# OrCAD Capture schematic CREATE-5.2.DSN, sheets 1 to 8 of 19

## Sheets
1 P02: ASPEN-MEM/USB/LCD: size Custom; title: ASPEN-MEM/LCD; rev: 3.0; note: Kinoma Create
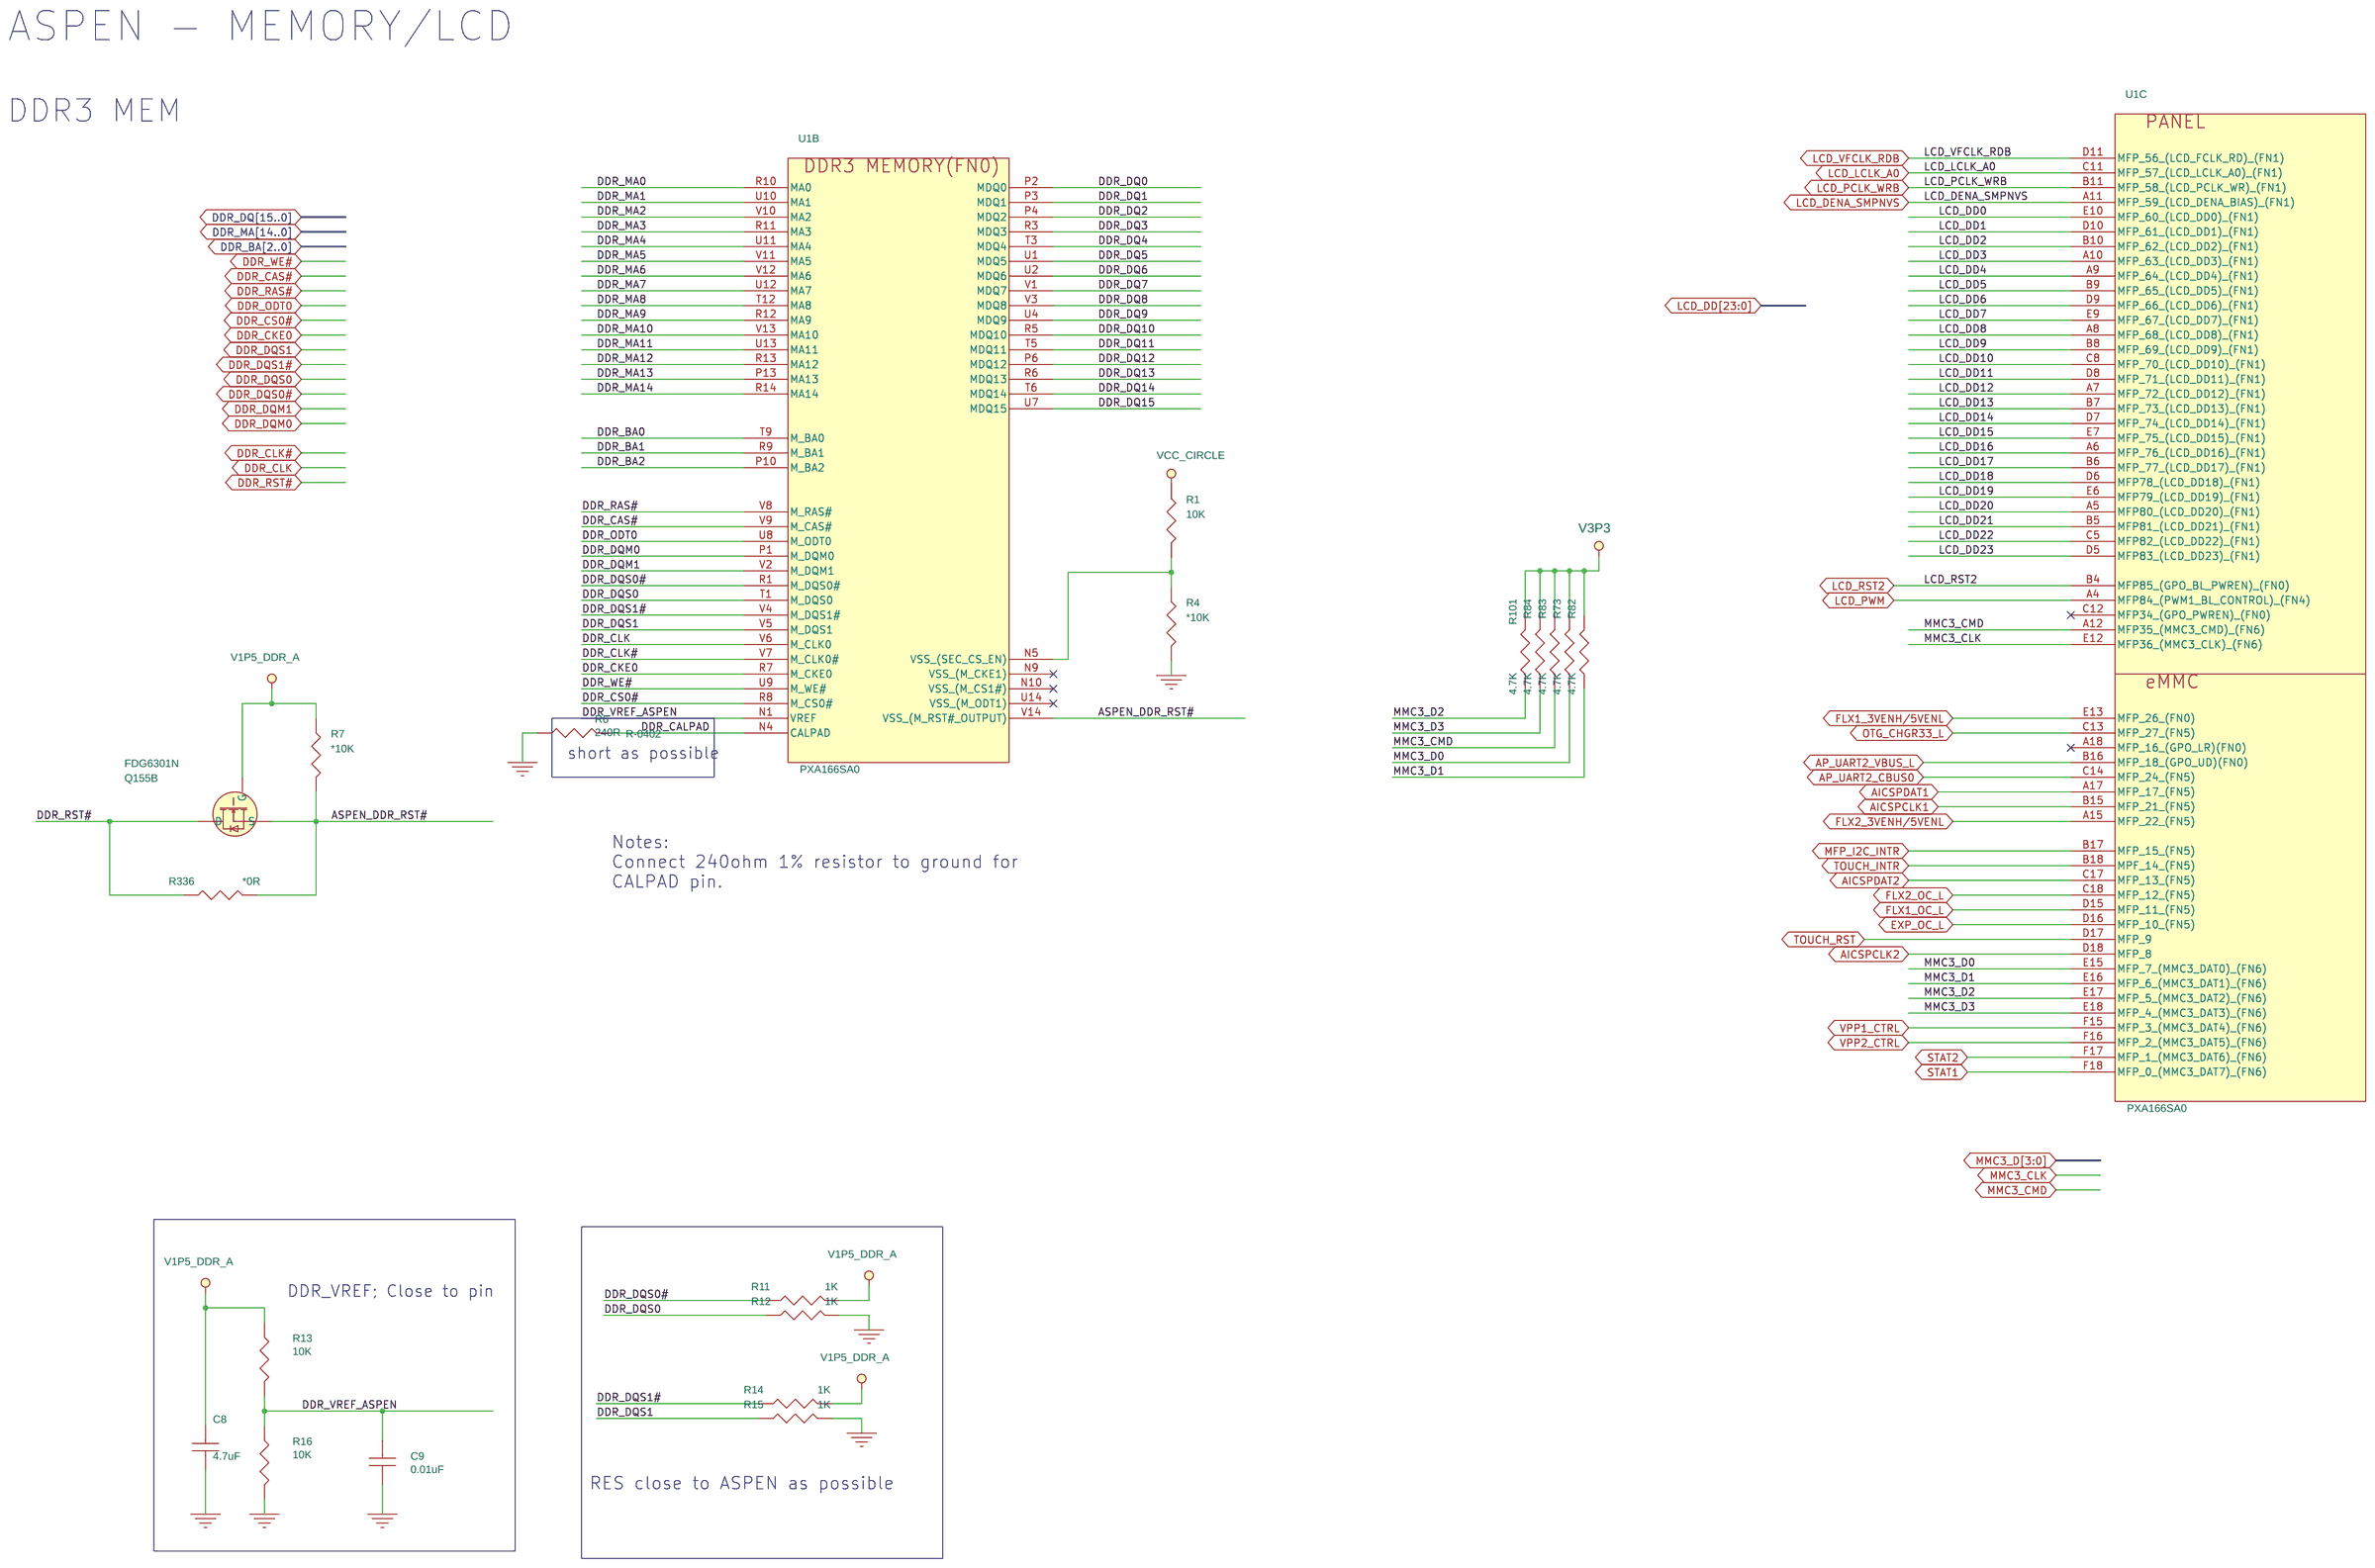
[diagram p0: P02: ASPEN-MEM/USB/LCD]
2 P04: ASPEN - Power: size Custom; title: ASPEN-Power
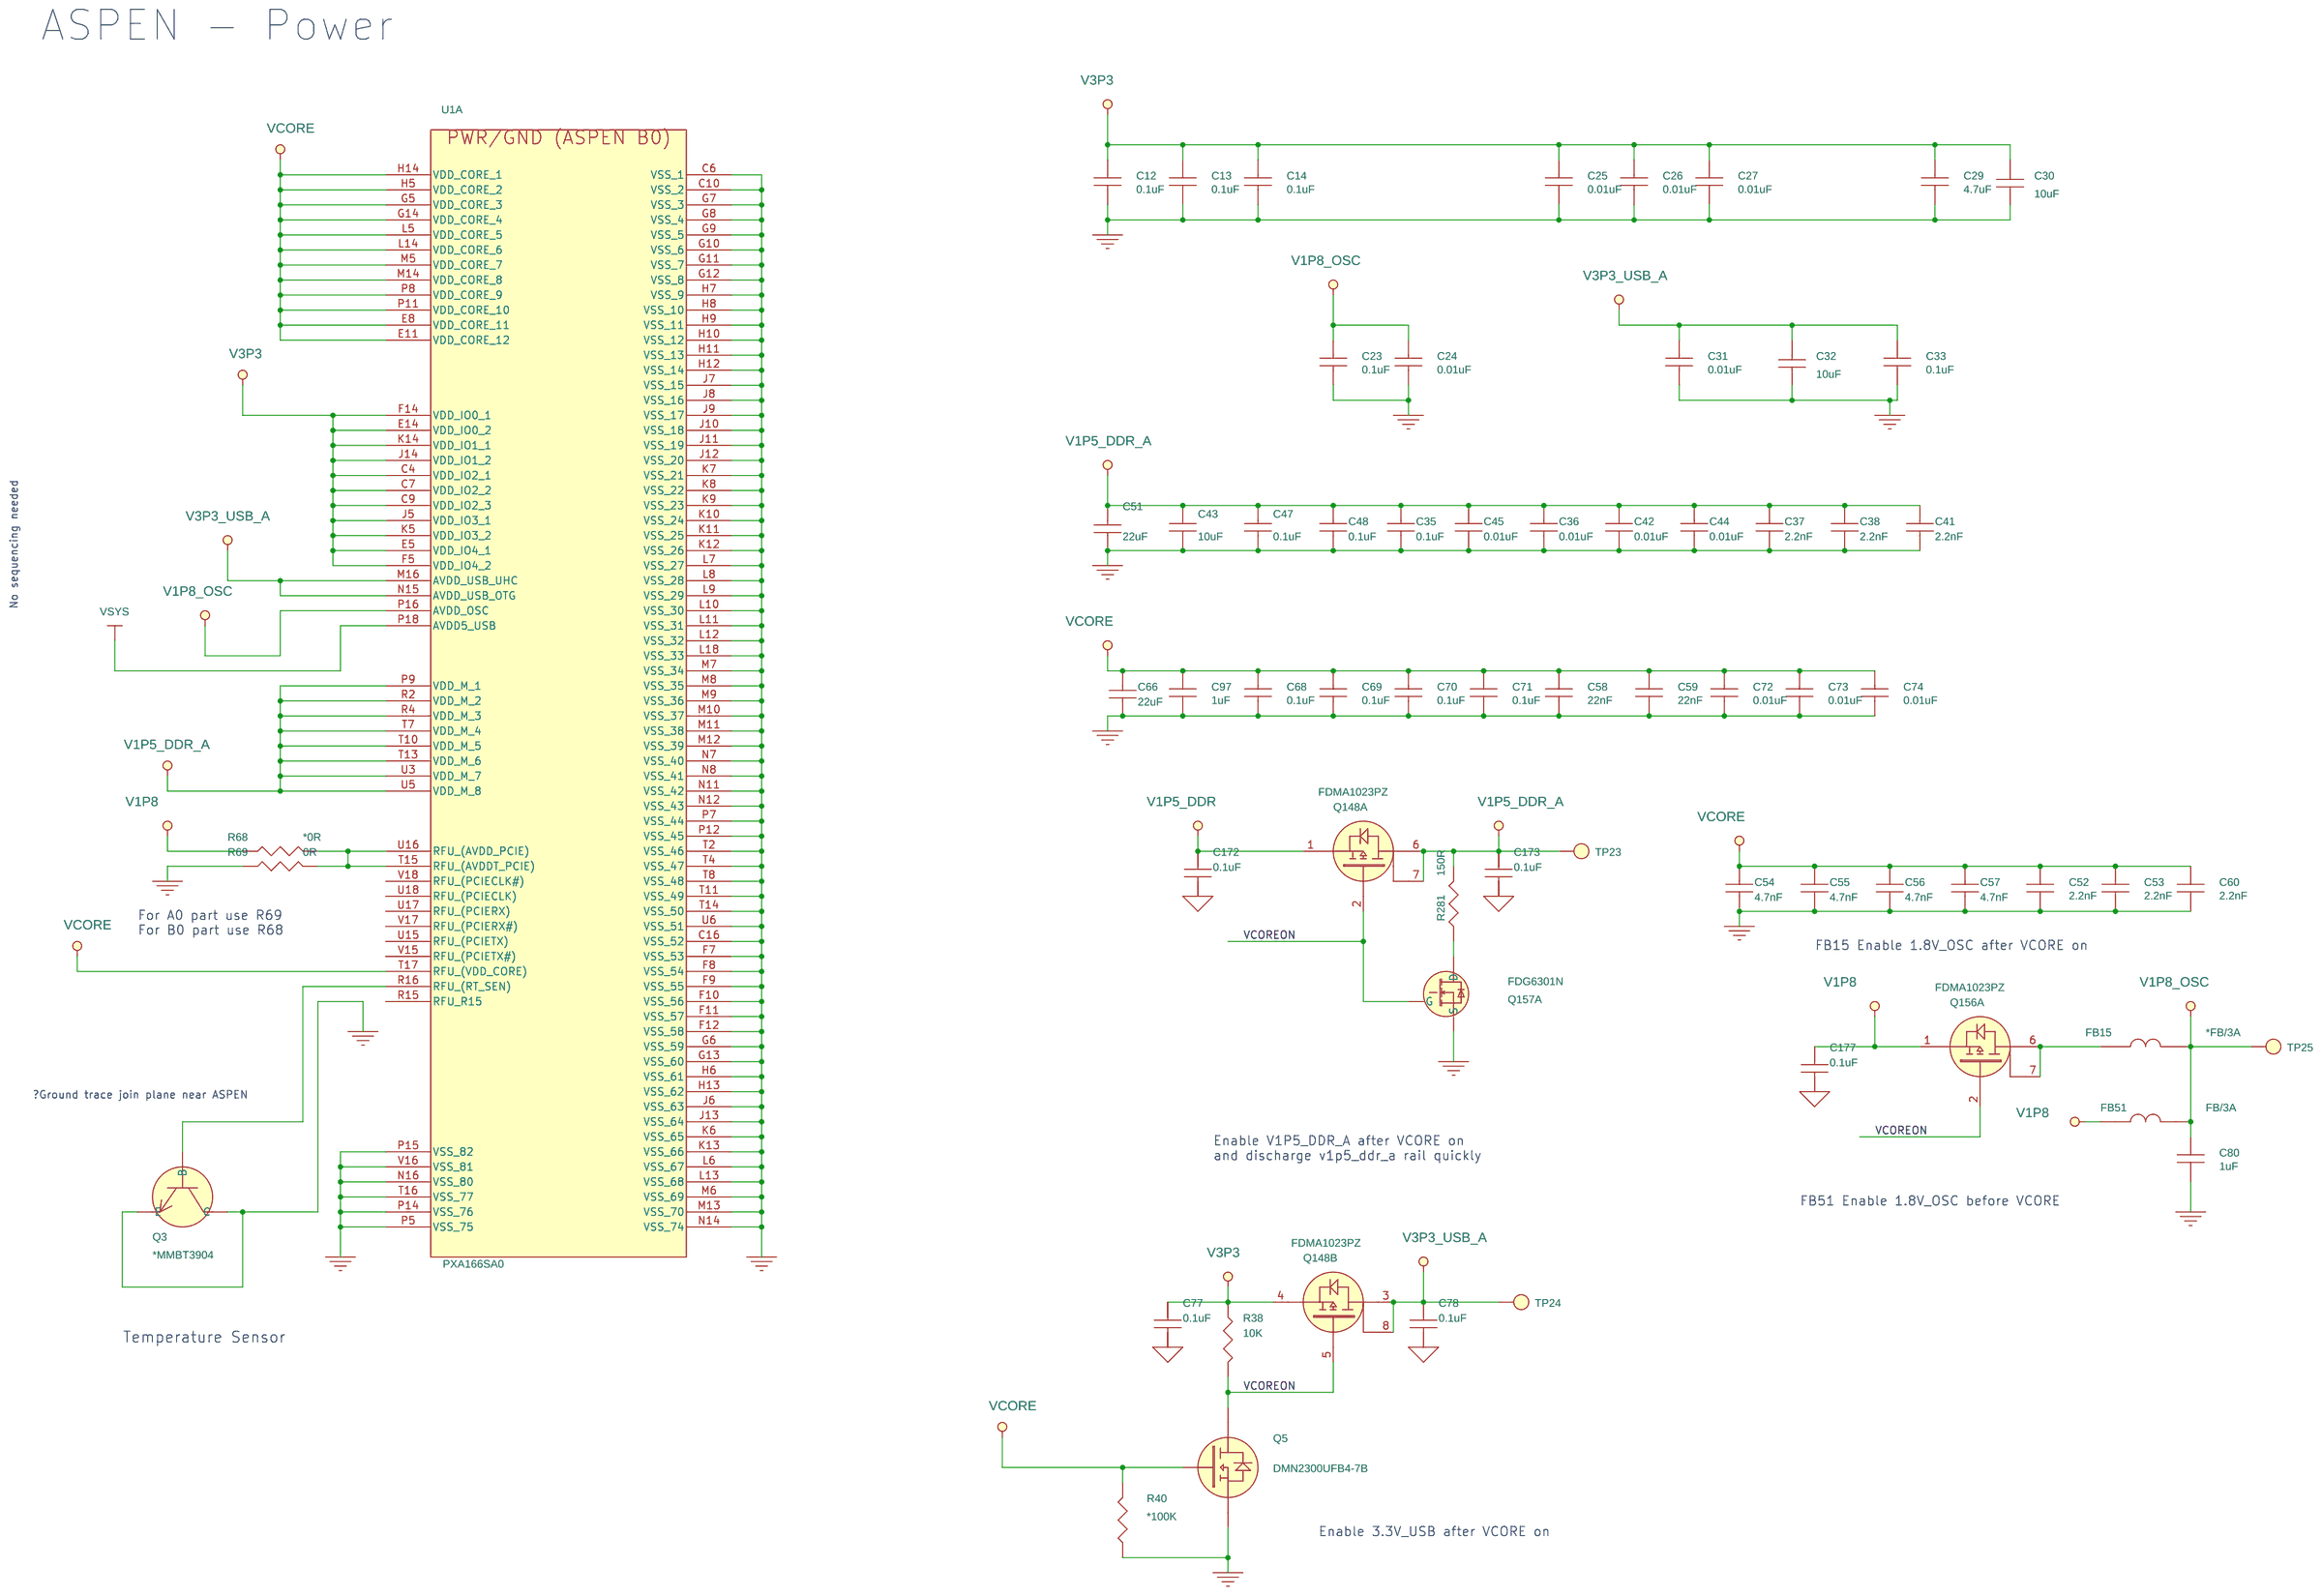
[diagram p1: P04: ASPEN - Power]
3 P06: Wifi 8887: size Custom; title: Wifi
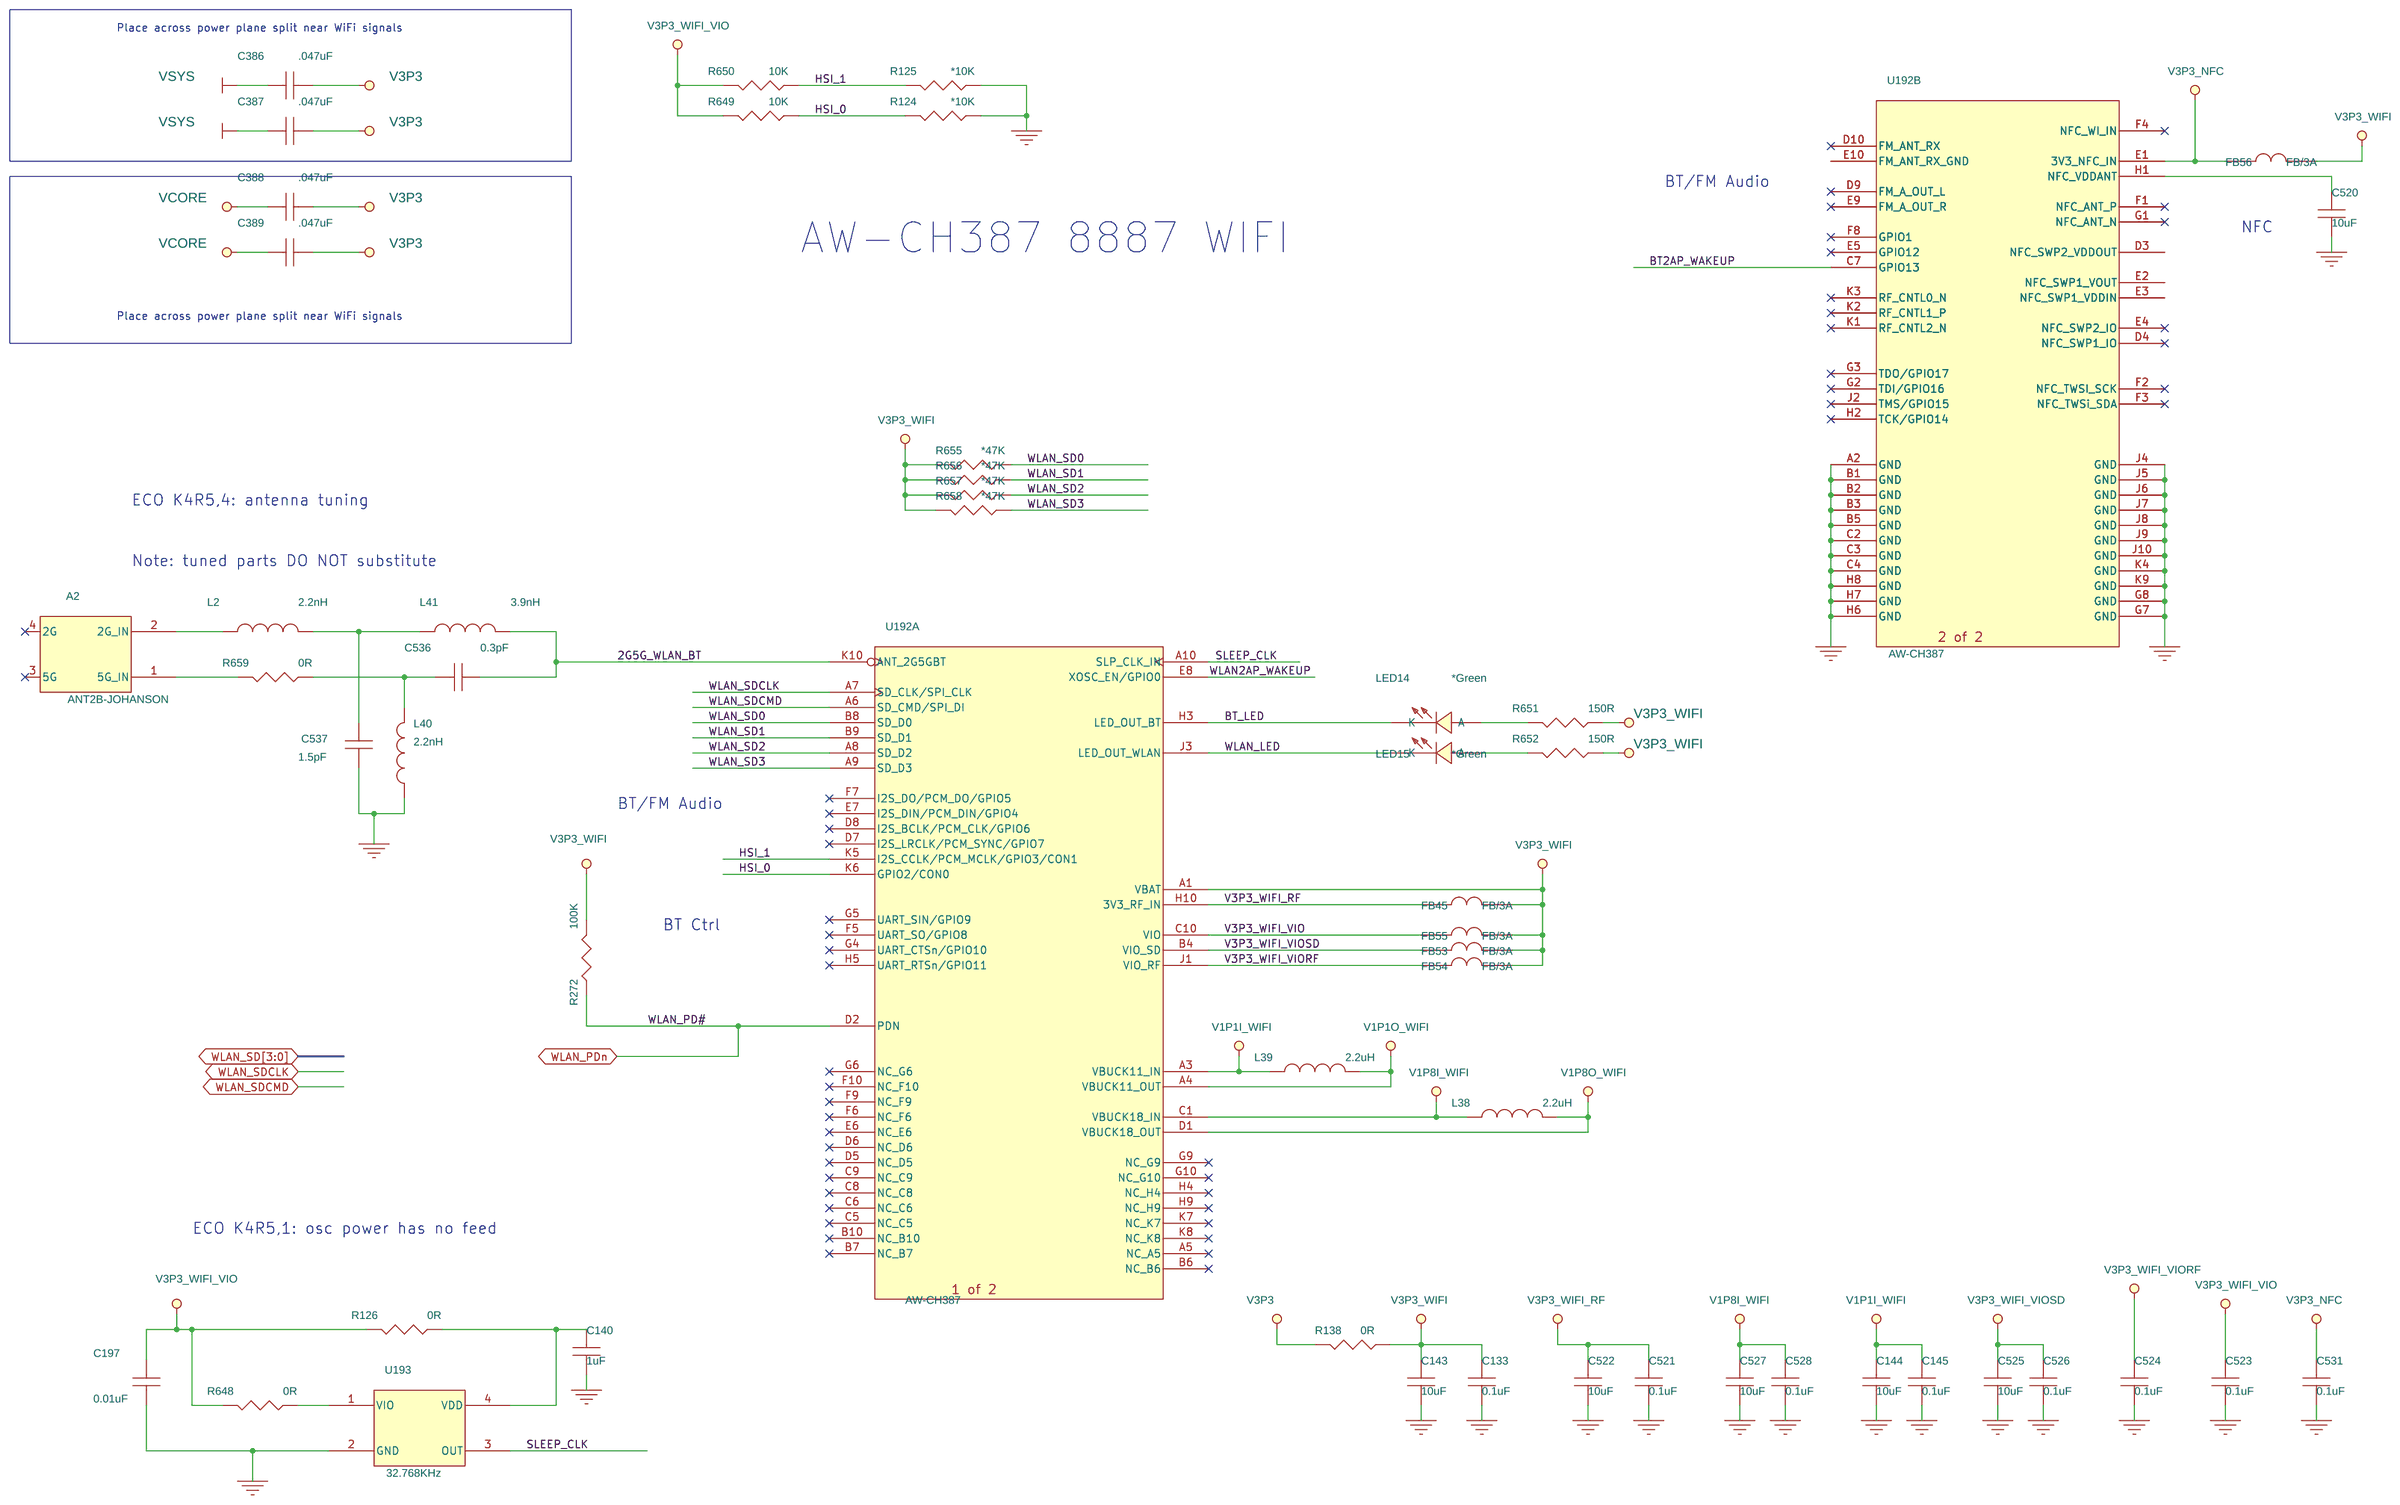
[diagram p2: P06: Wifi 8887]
4 P07: Audio: size Custom; title: Audio
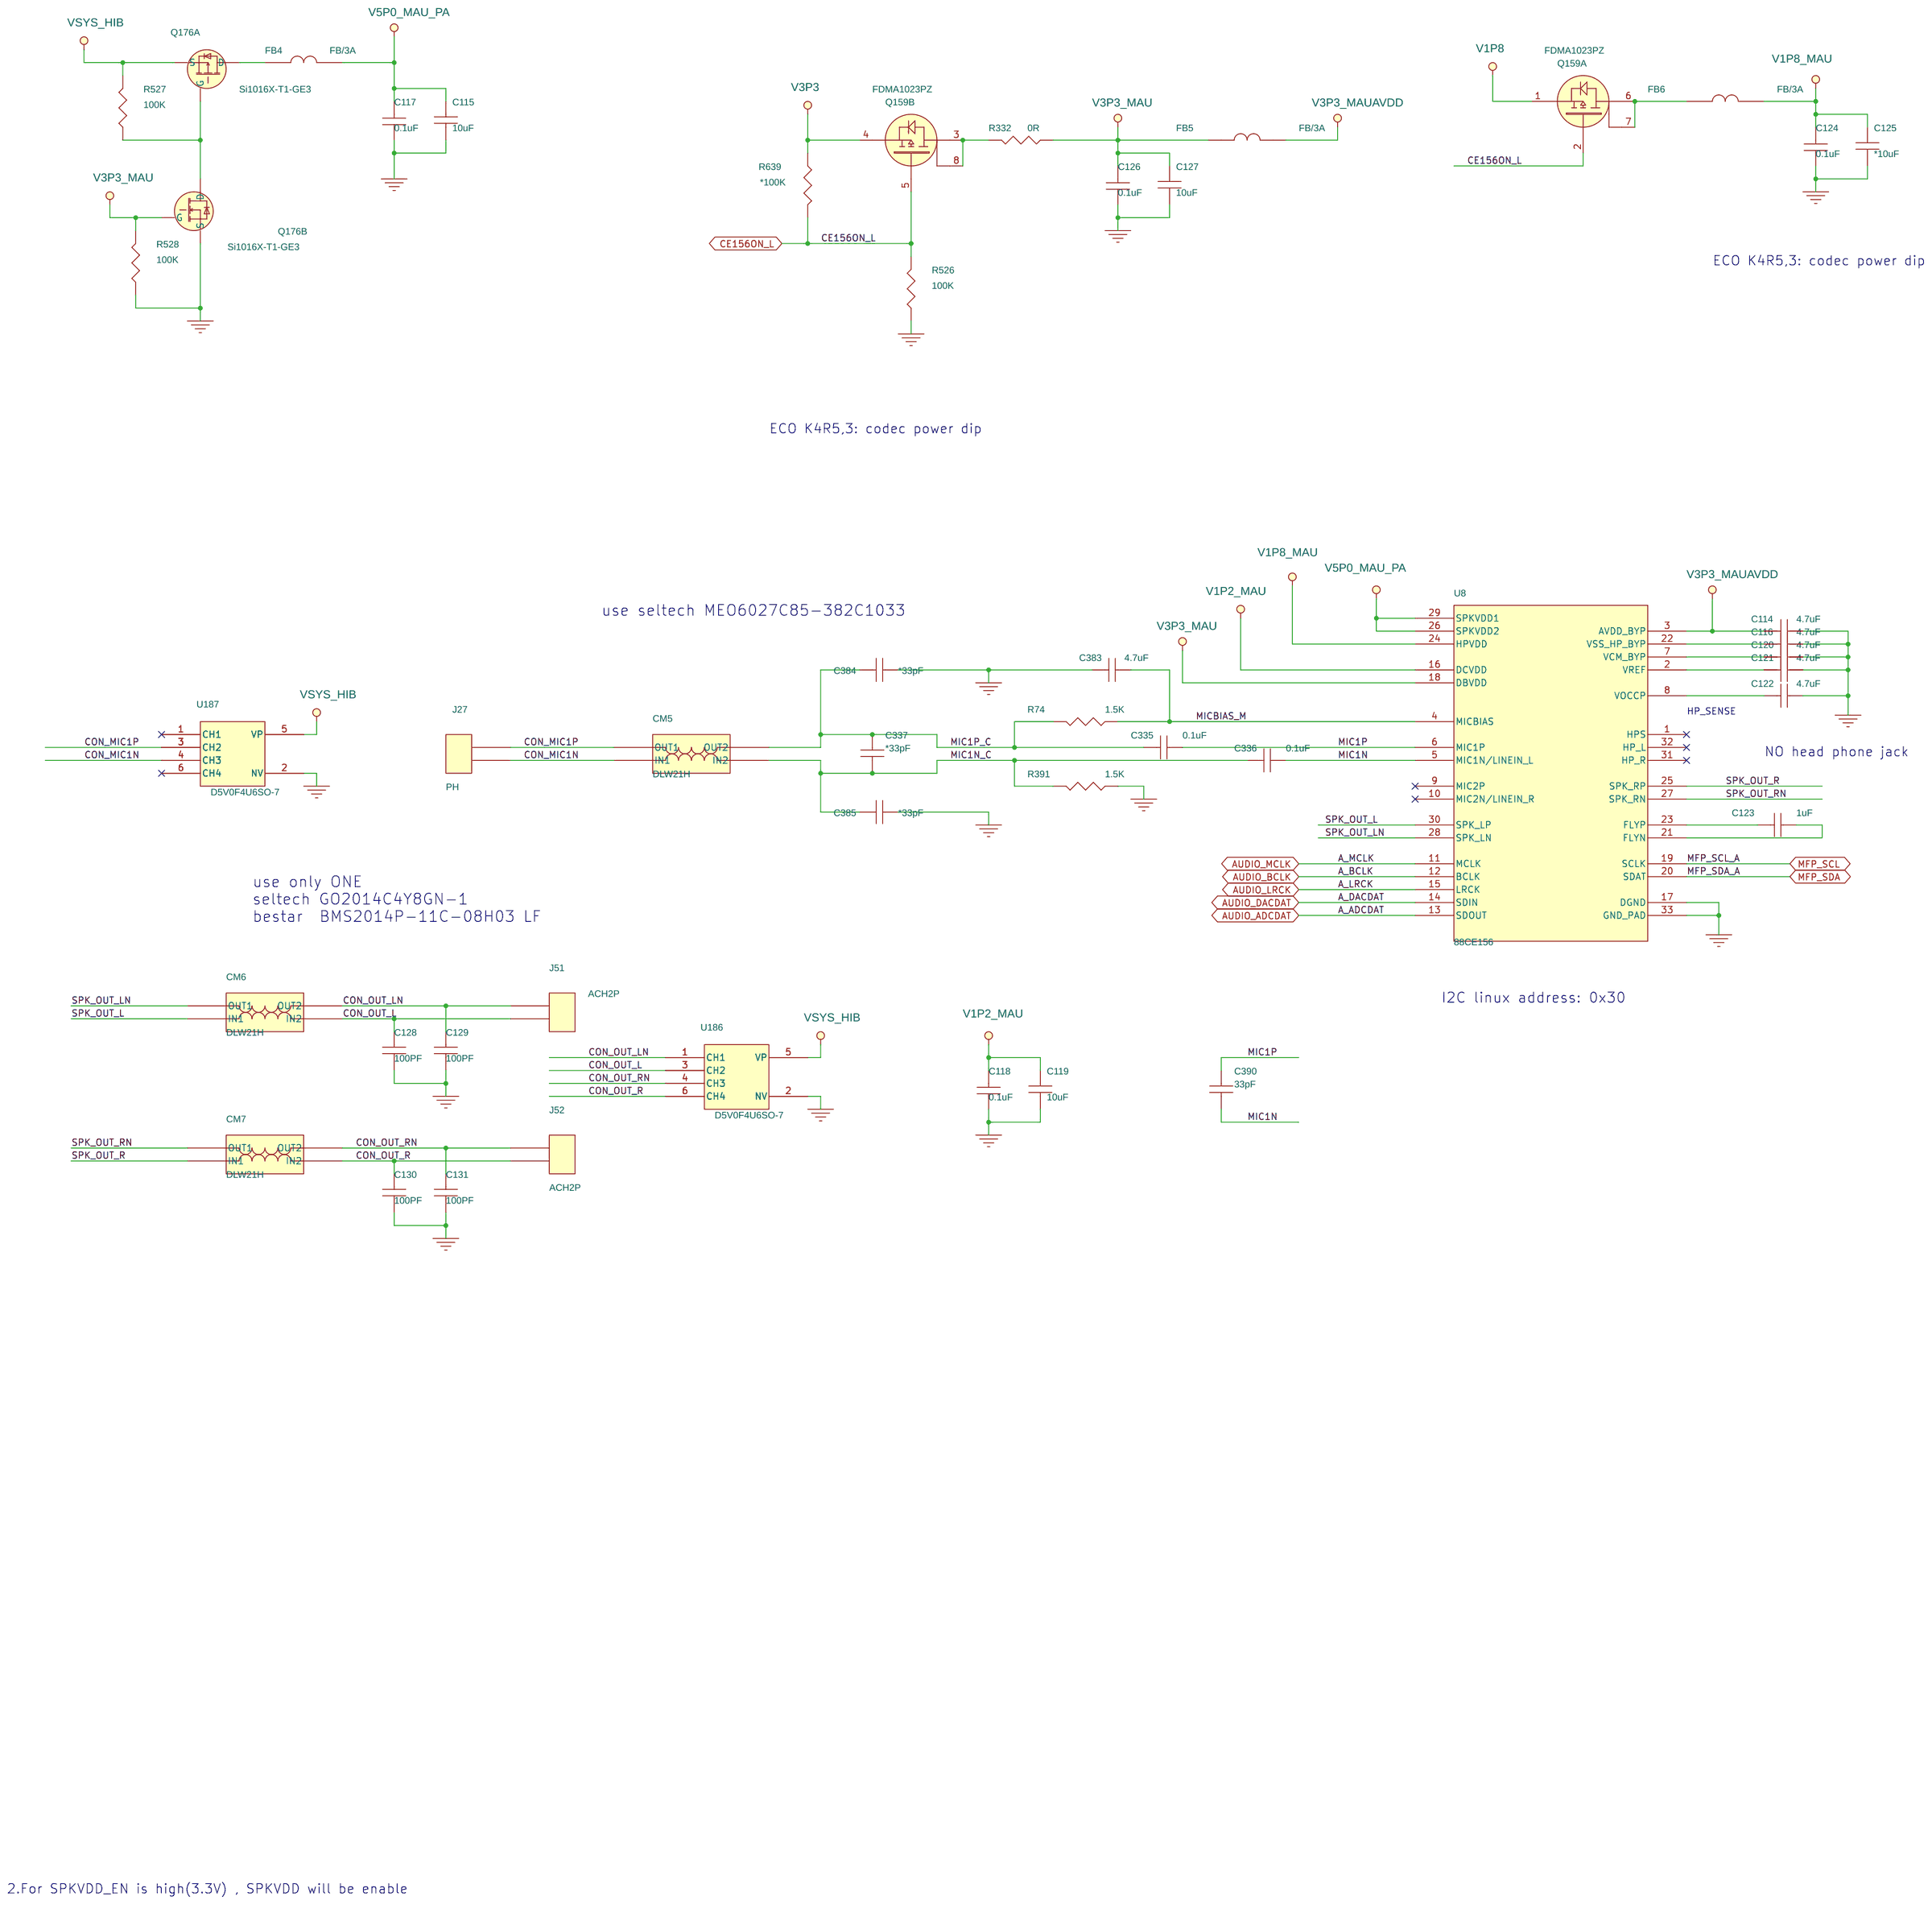
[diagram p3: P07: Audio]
5 P05: DDR3 SPI SD: size Custom; title: DDR3 SDRAM
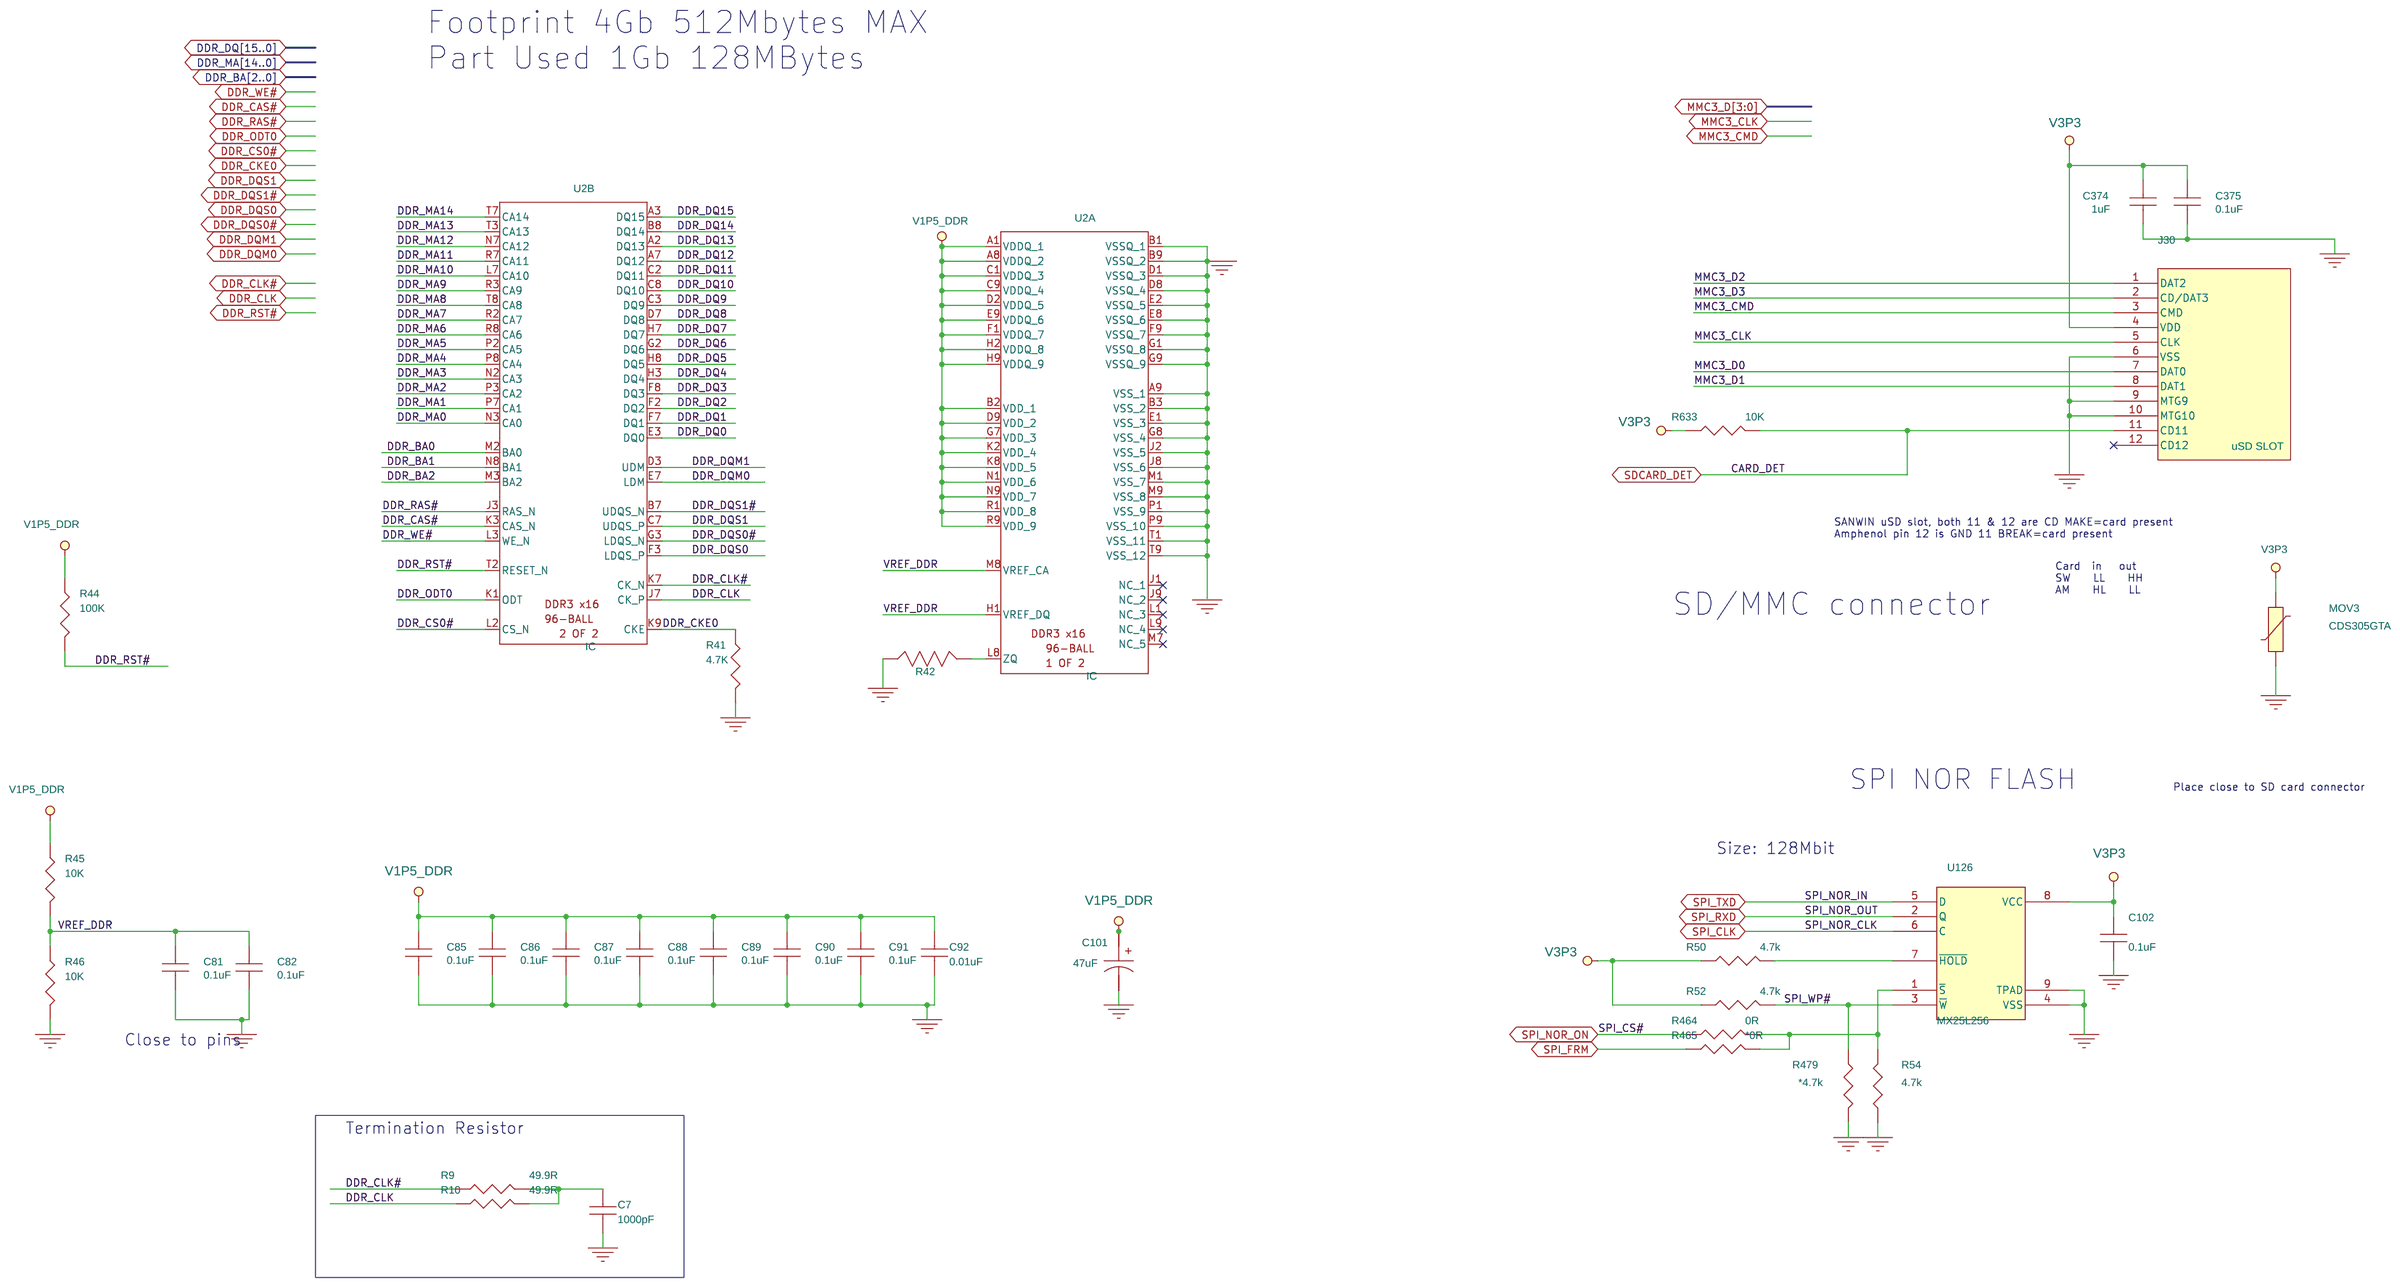
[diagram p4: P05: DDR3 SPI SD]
6 P08: LCD connections: size Custom; title: LCD & Touch
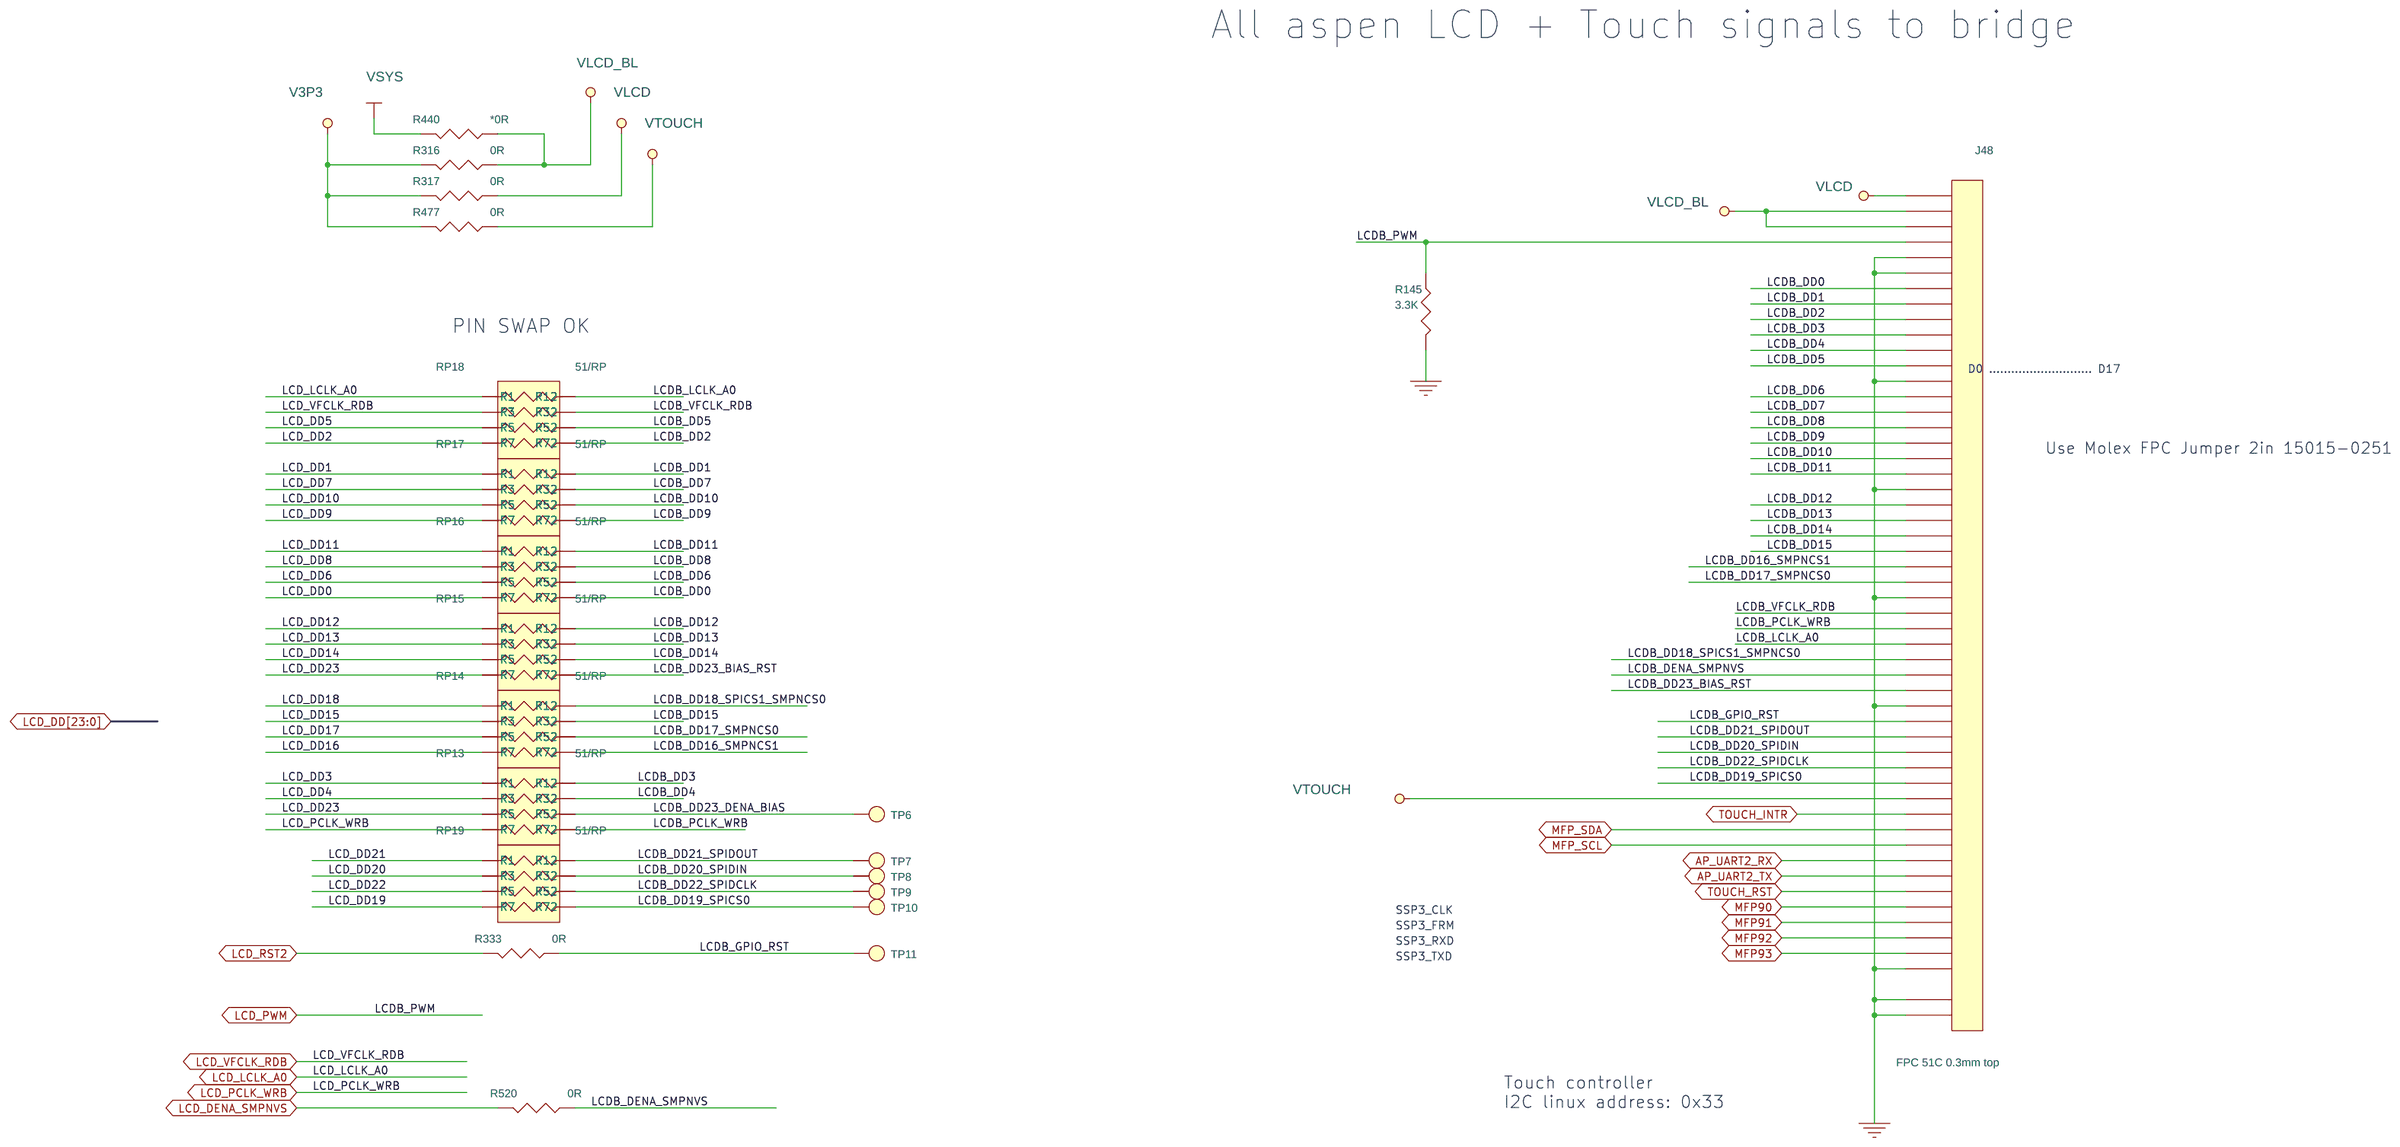
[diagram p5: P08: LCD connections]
7 P17: PIC Programmer: size B; title: PIC Programmer
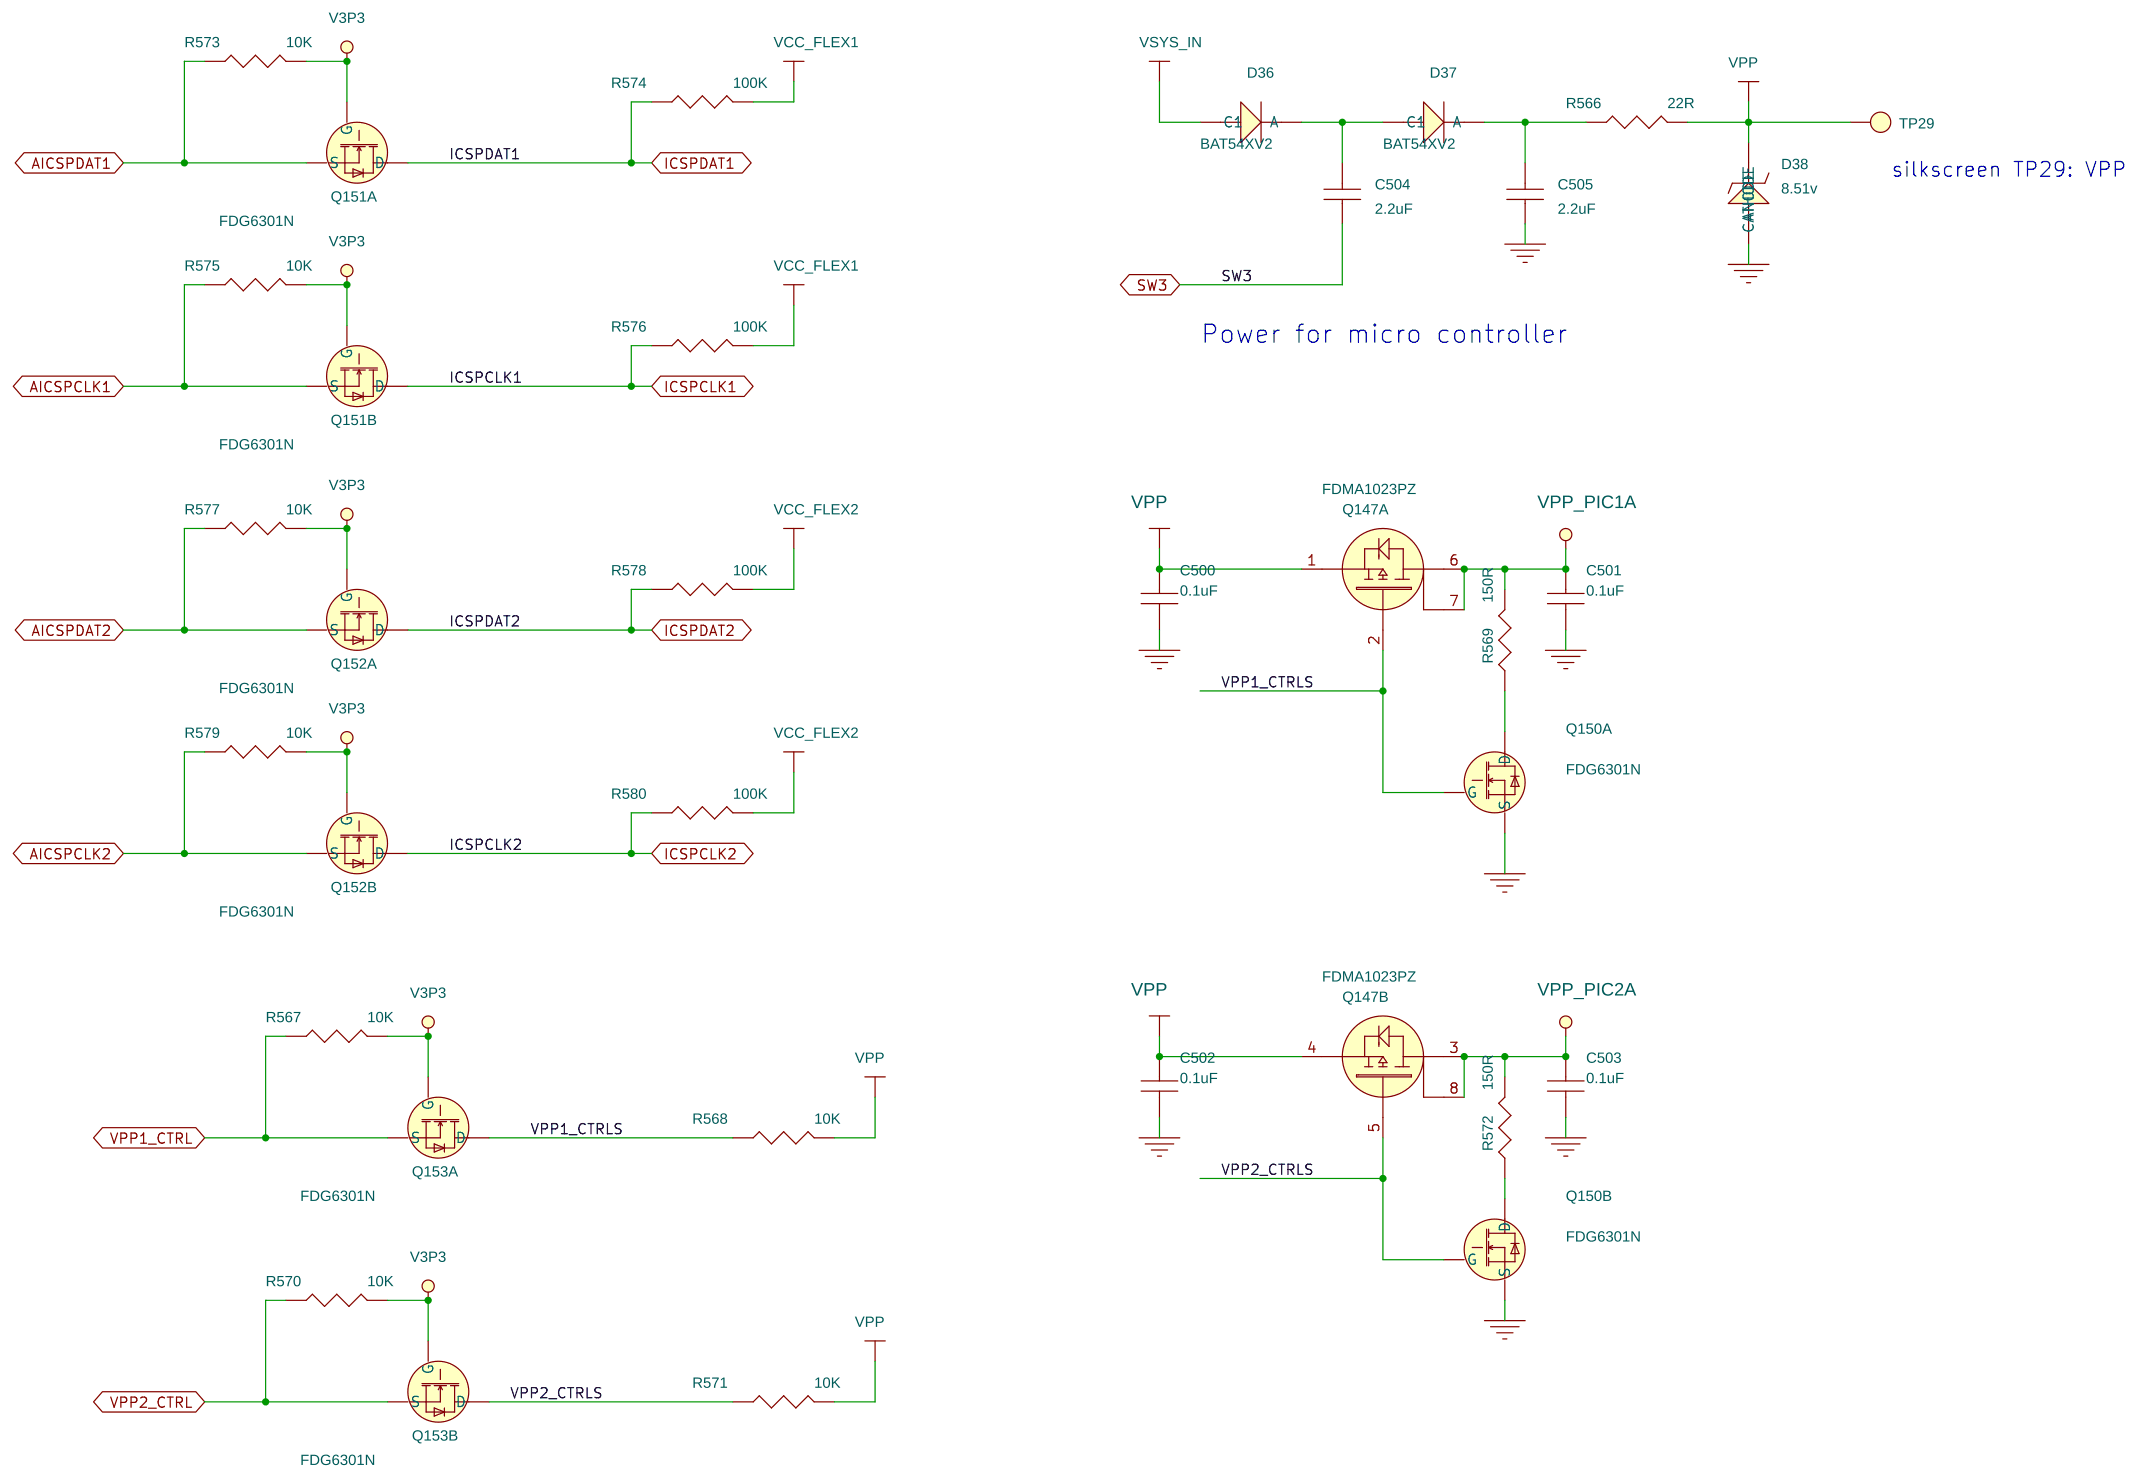
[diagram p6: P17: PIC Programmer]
8 P13: Debug + console: size Custom; title: Debug/Console
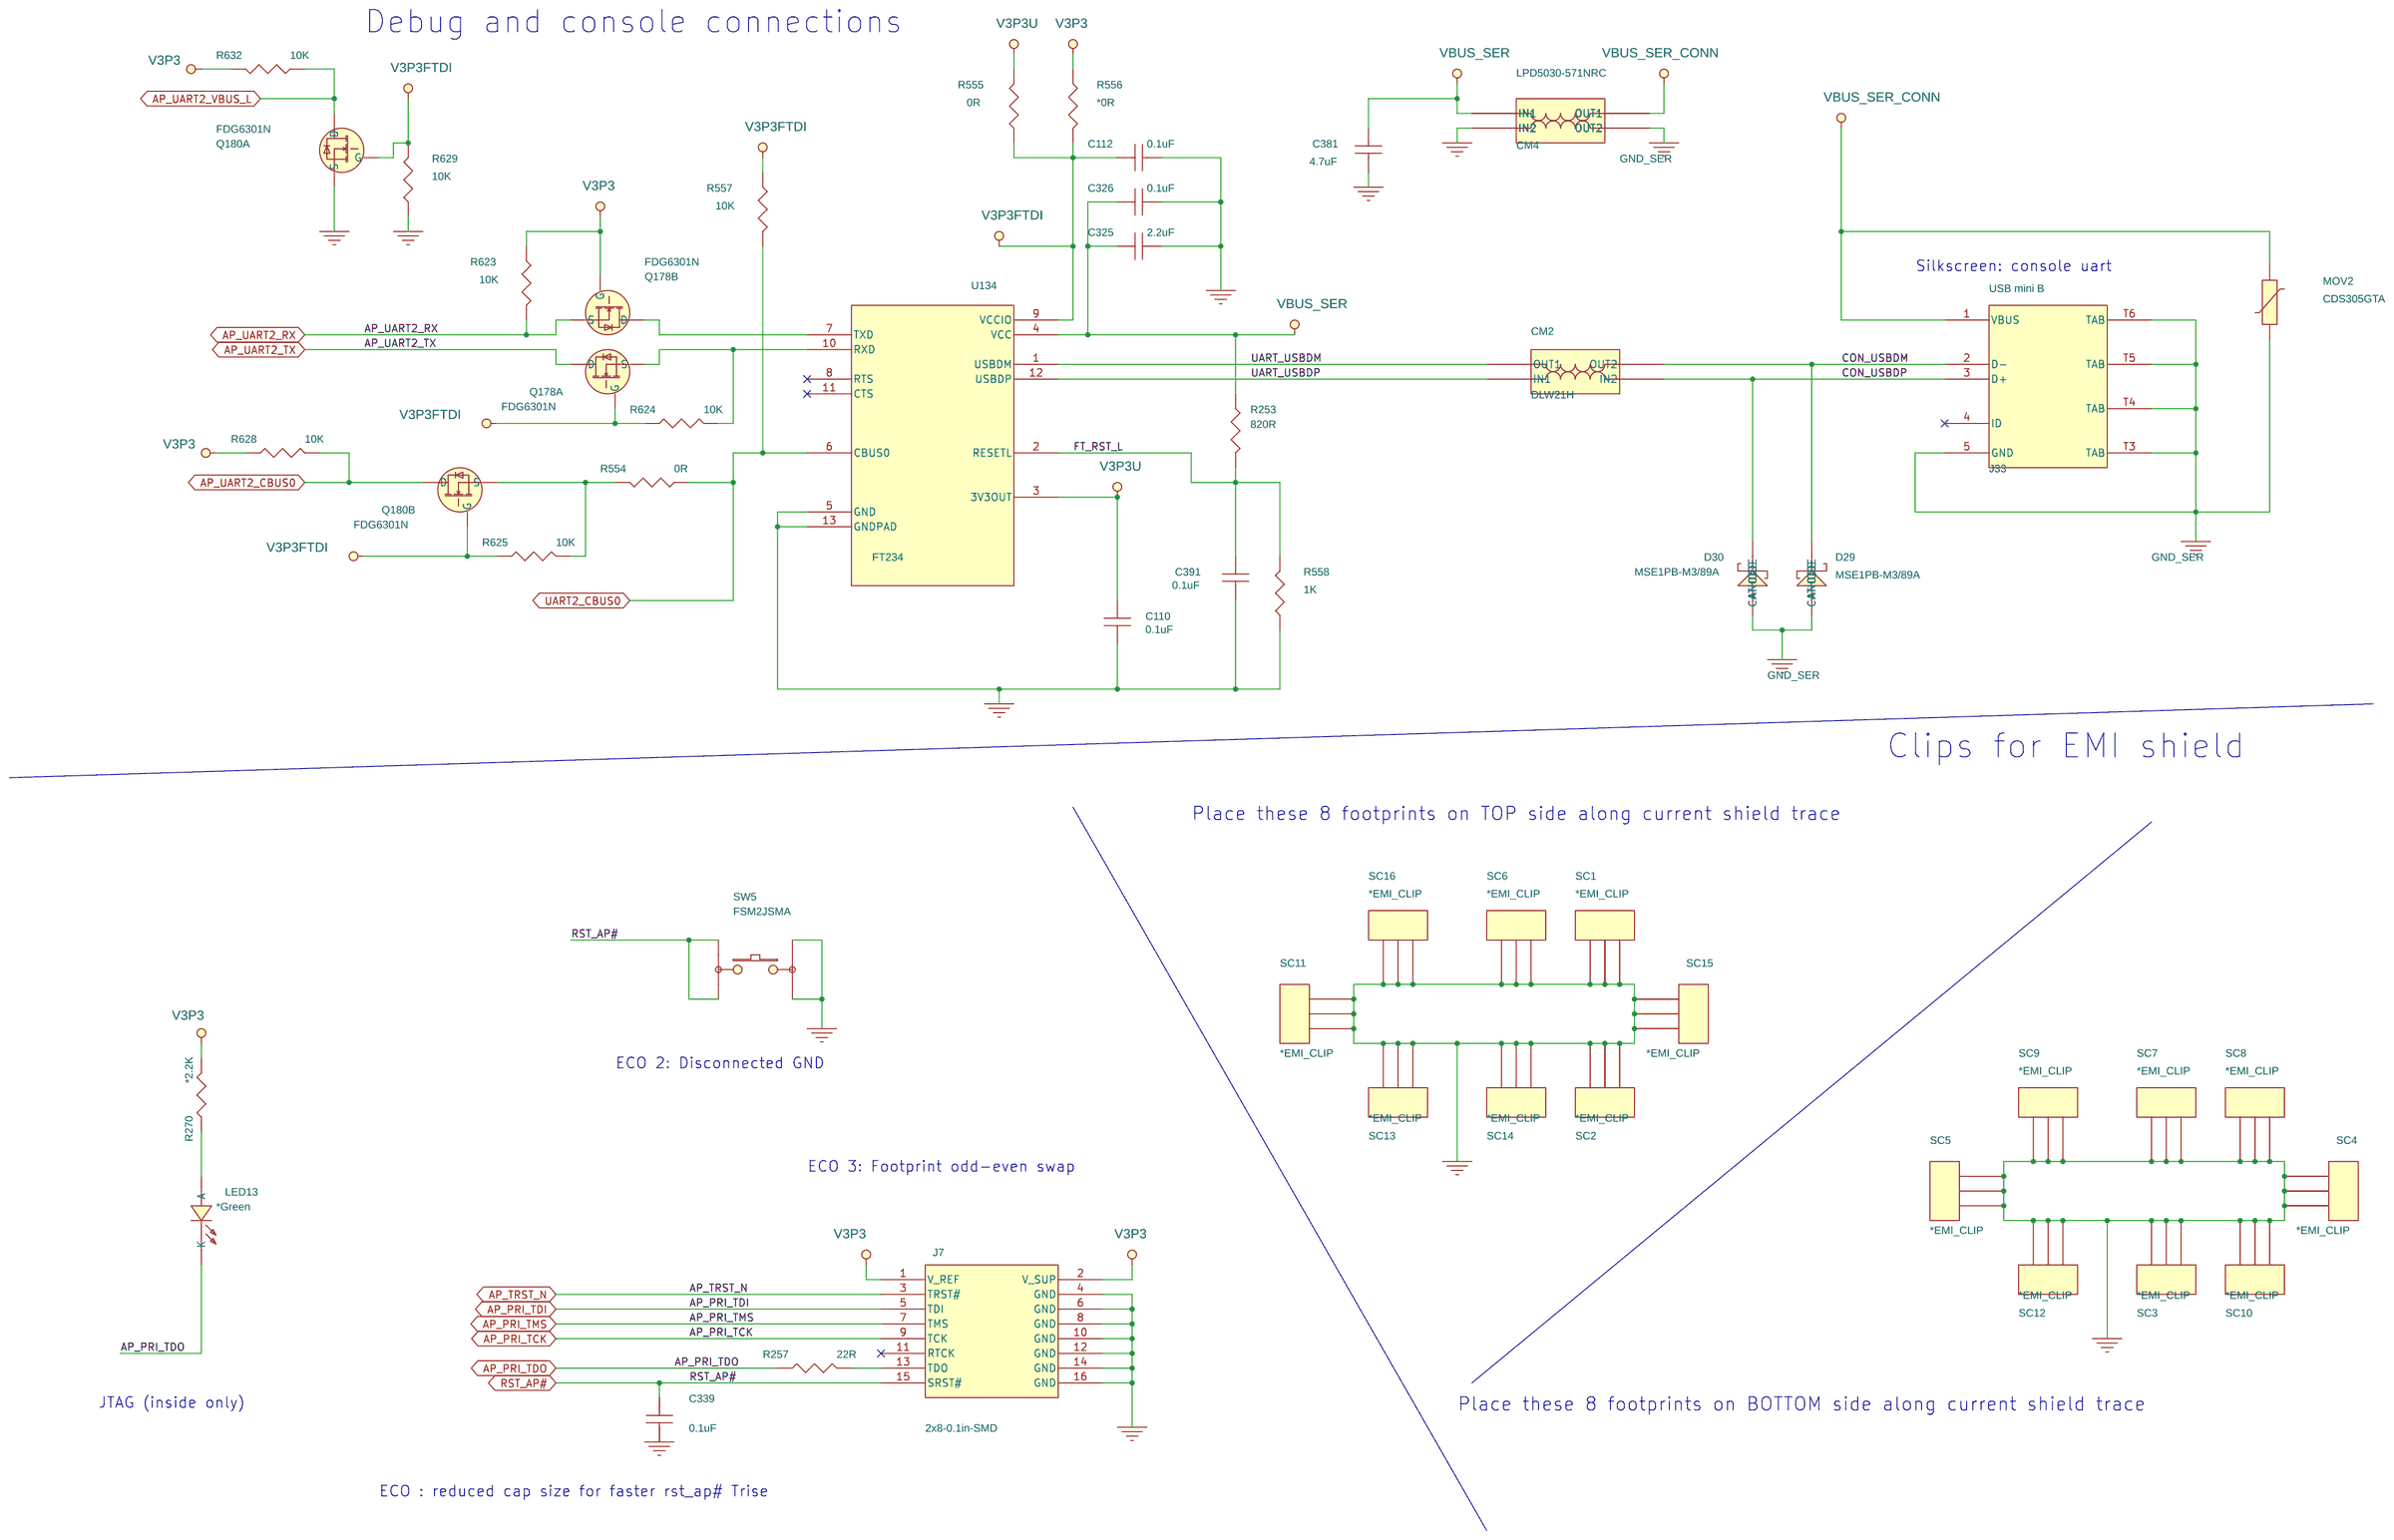
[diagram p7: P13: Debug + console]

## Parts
sheet P02: ASPEN-MEM/USB/LCD
C8  4.7uF  [C-0805]
C9  0.01uF  [C-0402]
Q155  FDG6301N  [SC70-6]  (sections A,B)
R1  10K  [R-0402]
R4  *10K  [R-0402]
R6  240R  [R-0402]
R7  *10K  [R-0402]
R11  1K  [R-0402]
R12  1K  [R-0402]
R13  10K  [R-0402]
R14  1K  [R-0402]
R15  1K  [R-0402]
R16  10K  [R-0402]
R73  4.7K  [R-0402]
R82  4.7K  [R-0402]
R83  4.7K  [R-0402]
R84  4.7K  [R-0402]
R101  4.7K  [R-0402]
R336  *0R  [R-0402]
sheet P03: ASPEN-AUDIO/SDIO/MISC
Q156  FDMA1023PZ  [WDFN6]  (sections A,B)
U1  PXA166SA0  [fbga-18x18-320]  (sections A,B,C,D,E,F)
sheet P04: ASPEN - Power
C12  0.1uF  [C-0402]
C13  0.1uF  [C-0402]
C14  0.1uF  [C-0402]
C23  0.1uF  [C-0402]
C24  0.01uF  [C-0402]
C25  0.01uF  [C-0402]
C26  0.01uF  [C-0402]
C27  0.01uF  [C-0402]
C29  4.7uF  [C-0805]
C30  10uF  [C-0402]
C31  0.01uF  [C-0402]
C32  10uF  [C-0402]
C33  0.1uF  [C-0402]
C35  0.1uF  [C-0402]
C36  0.01uF  [C-0402]
C37  2.2nF  [C-0402]
C38  2.2nF  [C-0402]
C41  2.2nF  [C-0402]
C42  0.01uF  [C-0402]
C43  10uF  [C-0402]
C44  0.01uF  [C-0402]
C45  0.01uF  [C-0402]
C47  0.1uF  [C-0402]
C48  0.1uF  [C-0402]
C51  22uF  [C-0603]
C52  2.2nF  [C-0402]
C53  2.2nF  [C-0402]
C54  4.7nF  [C-0402]
C55  4.7nF  [C-0402]
C56  4.7nF  [C-0402]
C57  4.7nF  [C-0402]
C58  22nF  [C-0402]
C59  22nF  [C-0402]
C60  2.2nF  [C-0402]
C66  22uF  [C-0603]
C68  0.1uF  [C-0402]
C69  0.1uF  [C-0402]
C70  0.1uF  [C-0402]
C71  0.1uF  [C-0402]
C72  0.01uF  [C-0402]
C73  0.01uF  [C-0402]
C74  0.01uF  [C-0402]
C77  0.1uF  [C-0402]
C78  0.1uF  [C-0402]
C80  1uF  [C0402]
C97  1uF  [C0402]
C172  0.1uF  [C-0402]
C173  0.1uF  [C-0402]
C177  0.1uF  [C-0402]
FB15  *FB/3A  [L-0603]
FB51  FB/3A  [L-0603]
Q3  *MMBT3904  [SOT23]
Q5  DMN2300UFB4-7B  [3-DFN]
Q148  FDMA1023PZ  [WDFN6]  (sections A,B)
Q157  FDG6301N  [SC70-6]  (section A)
R38  10K  [R-0402]
R40  *100K  [R-0402]
R68  *0R  [R-0402]
R69  0R  [R-0402]
R281  150R  [R-0402]
TP23  *T_POINT  [TP040]
TP24  *T_POINT  [TP040]
TP25  *T_POINT  [TP040]
sheet P05: DDR3 SPI SD
C7  1000pF  [C-0402]
C81  0.1uF  [C-0402]
C82  0.1uF  [C-0402]
C85  0.1uF  [C-0402]
C86  0.1uF  [C-0402]
C87  0.1uF  [C-0402]
C88  0.1uF  [C-0402]
C89  0.1uF  [C-0402]
C90  0.1uF  [C-0402]
C91  0.1uF  [C-0402]
C92  0.01uF  [C-0402]
C101  47uF  [C-1206]
C102  0.1uF  [C-0402]
C374  1uF  [C0402]
C375  0.1uF  [C-0402]
J30  uSD SLOT  [uSDCARD-push]
MOV3  CDS305GTA  [D0603]
R9  49.9R  [R-0402]
R10  49.9R  [R-0402]
R41  4.7K  [R-0402]
R42  240R  [R-0402]
R44  100K  [R-0402]
R45  10K  [R-0402]
R46  10K  [R-0402]
R50  4.7k  [R-0402]
R52  4.7k  [R-0402]
R54  4.7k  [R-0402]
R464  0R  [R-0402]
R465  *0R  [R-0402]
R479  *4.7k  [R-0402]
R633  10K  [R-0402]
U2  DDR3_X16_BGA96  [DDR3-96]  (sections A,B)
U126  MX25L256  [qfn-8x6-8s]
sheet P06: Wifi 8887
A2  ANT2B-JOHANSON  [JHS_ABGN]
C133  0.1uF  [C-0402]
C140  1uF  [C0402]
C143  10uF  [C-0402]
C144  10uF  [C-0402]
C145  0.1uF  [C-0402]
C197  0.01uF  [C-0402]
C386  .047uF  [C-0402]
C387  .047uF  [C-0402]
C388  .047uF  [C-0402]
C389  .047uF  [C-0402]
C520  10uF  [C-0402]
C521  0.1uF  [C-0402]
C522  10uF  [C-0402]
C523  0.1uF  [C-0402]
C524  0.1uF  [C-0402]
C525  10uF  [C-0402]
C526  0.1uF  [C-0402]
C527  10uF  [C-0402]
C528  0.1uF  [C-0402]
C531  0.1uF  [C-0402]
C536  0.3pF  [C-0402]
C537  1.5pF  [C-0402]
FB45  FB/3A  [L-0603]
FB53  FB/3A  [L-0603]
FB54  FB/3A  [L-0603]
FB55  FB/3A  [L-0603]
FB56  FB/3A  [L-0603]
L2  2.2nH  [L-0402]
L38  2.2uH  [L2520S]
L39  2.2uH  [L2520S]
L40  2.2nH  [L-0402]
L41  3.9nH  [L-0402]
LED14  *Green  [LED-0603]
LED15  *Green  [LED-0603]
R124  *10K  [R-0402]
R125  *10K  [R-0402]
R126  0R  [R-0402]
R138  0R  [R-0603]
R272  100K  [R-0402]
R648  0R  [R-0402]
R649  10K  [R-0402]
R650  10K  [R-0402]
R651  150R  [R-0402]
R652  150R  [R-0402]
R655  *47K  [R0201]
R656  *47K  [R0201]
R657  *47K  [R0201]
R658  *47K  [R0201]
R659  0R  [R-0402]
U192  AW-CH387  [SIP-100]  (sections A,B)
U193  32.768KHz  [SG-3040]
sheet P07: Audio
C114  4.7uF  [C-0805]
C115  10uF  [C-0603]
C116  4.7uF  [C-0805]
C117  0.1uF  [C-0402]
C118  0.1uF  [C-0402]
C119  10uF  [C-0402]
C120  4.7uF  [C-0805]
C121  4.7uF  [C-0805]
C122  4.7uF  [C-0805]
C123  1uF  [C0402]
C124  0.1uF  [C-0402]
C125  *10uF  [C-0402]
C126  0.1uF  [C-0402]
C127  10uF  [C-0402]
C128  100PF  [C-0402]
C129  100PF  [C-0402]
C130  100PF  [C-0402]
C131  100PF  [C-0402]
C335  0.1uF  [C-0402]
C336  0.1uF  [C-0402]
C337  *33pF  [C-0402]
C383  4.7uF  [C-0805]
C384  *33pF  [C-0402]
C385  *33pF  [C-0402]
C390  33pF  [C-0402]
CM5  DLW21H  [FIL-2X1_2-4]
CM6  DLW21H  [FIL-2X1_2-4]
CM7  DLW21H  [FIL-2X1_2-4]
FB4  FB/3A  [L-0603]
FB5  FB/3A  [L-0603]
FB6  FB/3A  [L-0603]
J27  PH  [JST_PH2P_2MM]
J51  ACH2P  [JST_ACHSS_2P1_2MM]
J52  ACH2P  [JST_ACHSS_2P1_2MM]
Q159  FDMA1023PZ  [WDFN6]  (sections A,B)
Q176  Si1016X-T1-GE3  [SOT563]  (sections A,B)
R74  1.5K  [R-0402]
R332  0R  [R-0603]
R391  1.5K  [R-0402]
R526  100K  [R-0402]
R527  100K  [R-0402]
R528  100K  [R-0402]
R639  *100K  [R-0402]
U8  88CE156  [QFN32p-0_5-5X5X1MM]
U186  D5V0F4U6SO-7  [SC-74]
U187  D5V0F4U6SO-7  [SC-74]
sheet P08: LCD connections
J48  FPC 51C 0.3mm top  [FH35_51_0_3MM]
R145  3.3K  [R-0402]
R316  0R  [R-0402]
R317  0R  [R-0402]
R333  0R  [R-0402]
R440  *0R  [R-0402]
R477  0R  [R-0402]
R520  0R  [R-0402]
RP13  51/RP  [EXB28V]
RP14  51/RP  [EXB28V]
RP15  51/RP  [EXB28V]
RP16  51/RP  [EXB28V]
RP17  51/RP  [EXB28V]
RP18  51/RP  [EXB28V]
RP19  51/RP  [EXB28V]
TP6  *T_POINT  [TP]
TP7  *T_POINT  [TP]
TP8  *T_POINT  [TP]
TP9  *T_POINT  [TP]
TP10  *T_POINT  [TP]
TP11  *T_POINT  [TP]
sheet P13: Debug + console
C110  0.1uF  [C-0402]
C112  0.1uF  [C-0402]
C325  2.2uF  [C-0402]
C326  0.1uF  [C-0402]
C339  0.1uF  [C-0402]
C381  4.7uF  [C-0603]
C391  0.1uF  [C-0402]
CM2  DLW21H  [FIL-2X1_2-4]
CM4  LPD5030-571NRC  [LPD5030]
D29  MSE1PB-M3/89A  [MicroSMP]
D30  MSE1PB-M3/89A  [MicroSMP]
J7  2x8-0.1in-SMD  [SKT2x8_100MIL_SMD]
J33  USB mini B  [USB-MINI-B-MOLEX]
LED13  *Green  [LED-0603]
MOV2  CDS305GTA  [D0603]
Q178  FDG6301N  [SC70-6]  (sections A,B)
Q180  FDG6301N  [SC70-6]  (sections A,B)
R253  820R  [R-0402]
R257  22R  [R-0402]
R270  *2.2K  [R-0402]
R554  0R  [R-0402]
R555  0R  [R-0402]
R556  *0R  [R-0402]
R557  10K  [R-0402]
R558  1K  [R-0402]
R623  10K  [R-0402]
R624  10K  [R-0402]
R625  10K  [R-0402]
R628  10K  [R-0402]
R629  10K  [R-0402]
R632  10K  [R-0402]
SC1  *EMI_CLIP  [HW-S0991-46R]
SC2  *EMI_CLIP  [HW-S0991-46R]
SC3  *EMI_CLIP  [HW-S0991-46R]
SC4  *EMI_CLIP  [HW-S0991-46R]
SC5  *EMI_CLIP  [HW-S0991-46R]
SC6  *EMI_CLIP  [HW-S0991-46R]
SC7  *EMI_CLIP  [HW-S0991-46R]
SC8  *EMI_CLIP  [HW-S0991-46R]
SC9  *EMI_CLIP  [HW-S0991-46R]
SC10  *EMI_CLIP  [HW-S0991-46R]
SC11  *EMI_CLIP  [HW-S0991-46R]
SC12  *EMI_CLIP  [HW-S0991-46R]
SC13  *EMI_CLIP  [HW-S0991-46R]
SC14  *EMI_CLIP  [HW-S0991-46R]
SC15  *EMI_CLIP  [HW-S0991-46R]
SC16  *EMI_CLIP  [HW-S0991-46R]
SW5  FSM2JSMA  [FSM2JSMATR]
U134  FT234  [DFN12]
sheet P17: PIC Programmer
C500  0.1uF  [C-0402]
C501  0.1uF  [C-0402]
C502  0.1uF  [C-0402]
C503  0.1uF  [C-0402]
C504  2.2uF  [C-0402]
C505  2.2uF  [C-0402]
D36  BAT54XV2  [SOD-523F]
D37  BAT54XV2  [SOD-523F]
D38  8.51v  [sod323]
Q147  FDMA1023PZ  [WDFN6]  (sections A,B)
Q150  FDG6301N  [SC70-6]  (sections A,B)
Q151  FDG6301N  [SC70-6]  (sections A,B)
Q152  FDG6301N  [SC70-6]  (sections A,B)
Q153  FDG6301N  [SC70-6]  (sections A,B)
R566  22R  [R-0402]
R567  10K  [R-0201]
R568  10K  [R-0201]
R569  150R  [R-0402]
R570  10K  [R-0201]
R571  10K  [R-0201]
R572  150R  [R-0402]
R573  10K  [R-0201]
R574  100K  [R-0201]
R575  10K  [R-0201]
R576  100K  [R-0201]
R577  10K  [R-0201]
R578  100K  [R-0201]
R579  10K  [R-0201]
R580  100K  [R-0201]
TP29  *T_POINT  [TP040]

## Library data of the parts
C8 C114 C116 C120-C122 C383 = CAP_NP_0: Desc: CAP 4.7uF 10% 0805 25V X5R; Part Num: C0805C475K3PACTU; Vendor: kemet
C9 = CAP_NP_0: Desc: CAP CER 10000PF 16V 10% X7R 0402; Mfr: Murata; Part Num: GRM155R71C103KA01D; Vendor: Murata
Q150 Q155 Q157 = NMOS-DUAL6-sc70: Desc: MOSFET 2N-CH 25V 0.22A SC70-6; Vendor: Fairchild; x: MOSFET 2N-CH 25V 0.22A SC70-6
R1 R4 R7 = RESISTOR: Desc: RES 10K OHM 1/10W 5% 0402 SMD; Part Num: ERJ-2GEJ103X; Vendor: Panasonic
R6 = Res_0: Desc: RES 240 OHM 1/10W 1% 0402 SMD; Mfr: Generic; Part Num: ERJ-2RKF2400X; Vendor: Panasonic
R11 R12 R14 R15 = Res_0: Desc: RES 1K OHM 1/10W 1% 0402 SMD; Mfr: Generic; Part Num: ERJ-2RKF1001X; Vendor: Panasonic; d: RES 1K OHM 1/10W 1% 0402 SMD
R13 R16 R45 R46 R124 R125 R633 R649 R650 = Res_0: Desc: RES 10K OHM 1/10W 5% 0402 SMD; Mfr: Generic; Part Num: ERJ-2GEJ103X; Vendor: Panasonic
R50 R52 R54 R73 R82 R101 R479 = Res_0: Desc: RES 4.7K OHM 1/10W 5% 0402 SMD; Part Num: ERJ-2GEJ472X; Vendor: Panasonic
R83 R84 = Res_0: Desc: RES 4.7K OHM 1/10W 5% 0402 SMD; Part Num: ERJ-2GEJ472X; Part Number: R4720402; Vendor: Panasonic
R316 R317 R333 R336 R440 R477 R520 = Res_0: Desc: RES 0.0 OHM 1/10W 0402 SMD; Mfr: Generic; Part Num: ERJ-2GE0R00X; Vendor: Panasonic; ccc: RES 0.0 OHM 1/10W 0402 SMD
Q147 Q148 Q156 Q159 = FDMA1029PZ: Desc: MOSFET 2P-CH 20V 3.7A MICROFET; Vendor: Fairchild
U1 = PXA168_1: Desc: IC App Processor SOC; Part Num: 88AP166SA0-BJD2C008; Vendor: Marvell
C12-C14 C23 C33 C35 C47 C48 C68-C71 C375 = CAP_NP_1: Desc: CAP CER .10UF 10V X7R 0402; Part Num: C1005X7R1A104K; Vendor: TDK
C24-C27 C31 C36 C42 C44 C45 C72-C74 = CAP_NP_1: Desc: CAP CER 10000PF 16V 10% X7R 0402; Mfr: Murata; Part Num: GRM155R71C103KA01D; Vendor: Murata
C29 = CAP_NP_1: Desc: CAP 4.7uF 10% 0805 25V X5R; Part Num: C0805C475K3PACTU; Vendor: kemet
C30 C32 C43 C143 C144 C520 C522 C525 C527 = CAP_NP_0: Desc: CAP CER 10UF 6.3V 20% X5R 0402; Part Num: C1005X5R0J106M050BC; Vendor: TDK
C37 C38 C41 C52 C53 C60 = CAP_NP_1: Desc: CAP CER 2200PF 25V 10% X7R 0402; Part Num: 04023C222KAT2A; Vendor: avx; mfg: avx
C51 C66 = CAP_NP_0: Desc: CAP CER 22UF 4V 20% X5R 0603; Part Num: AMK107BJ226MA-T; Vendor: Taiyo
C54-C57 = CAP_NP_1: Desc: CAP CER 4700PF 25V 10% X7R 0402; Part Num: 04023C472KAT2A; Vendor: AVX; mfg_pn: 04023C472KAT2A
C58 C59 = CAP_NP_1: Desc: CAP 22nF 10% 0402 10V X7R; Part Num: VJ0402Y223JXQCW1BC; Vendor: vishay; mfg: vishay; mfg_pn: VJ0402Y223JXQCW1BC
C77 C78 C172 C173 C177 C339 C500-C503 = CAP_NP_2: Desc: CAP CER .10UF 10V X7R 0402; Part Num: C1005X7R1A104K; Vendor: TDK; mfg: TDK; mfg_pn: C1005X7R1A104K
C80 C97 C374 = CAP_NP: Desc: CAP CER 1UF 10V 10% X5R 0402; Part Num: C1005X5R1A105K050BB; Vendor: TDK; ccc: CAP CER 1UF 10V 10% X5R 0402
FB4-FB6 FB15 FB45 FB51 FB53-FB56 = FERRITE_BEAD_0: Desc: FERRITE CHIP 120 OHM 3000MA 0603; Part Num: BLM18KG121TN1; Vendor: Murata
Q3 = NPN: Desc: Transistor NPN MMBT3904; Part Num: MMBT3904LT1G; Vendor: On Semi
Q5 = NMOS3: Desc: MOSFET N-CH 20V 1.3A 3DFN; Vendor: Diodes
R38 = R_0: Desc: RES 10K OHM 1/10W 5% 0402 SMD; Mfr: Generic; Part Num: ERJ-2GEJ103X; Vendor: Panasonic
R40 R526-R528 R639 = R_0: RES 100K OHM 1/20W 5% 0201 SMD; Desc: RES 100K OHM 1/16W 5% 0402 SMD; Mfr: Generic; Part Num: CRCW0402100KJNED; Vendor: Vishay
R68 R69 R464 R465 = Res_0: Desc: RES 0.0 OHM 1/10W 0402 SMD; Mfr: Generic; Part Num: ERJ-2GE0R00X; Vendor: Panasonic
R281 R569 R572 = Res_0: Desc: RES 150 OHM 1/16W 1% 0402 SMD; Part Num: MCR01MZPF1500; Vendor: Rohm
TP6-TP11 TP23-TP25 TP29 = T_POINT: Desc: SMT Test Point; Part Num: NA; Vendor: Test
C7 = CAP_NP_1: Desc: CAP 1nF 10% 0402 25V X7R; Part Num: C0402S102K3RACTU; Vendor: kemet; mfg: Kemet; mfg_pn: C0402S102K3RACTU
C81 C82 C85-C91 = CAP_NP_1: Desc: CAP CER .10UF 10V X7R 0402; Part Num: C1005X7R1A104K; Vendor: TDK; mfg: TDK; mfg_pn: C1005X7R1A104K
C92 = CAP_NP_1: Desc: CAP CER 10000PF 16V 10% X7R 0402; Mfr: Murata; Part Num: GRM155R71C103KA01D; Vendor: Murata; mfg: Murata; mfg_pn: GRM155R71C103KA01D
C101 = CAPACITOR_POL_0: Desc: CAP CER 47UF 4V X6S 1206; Part Num: GRM31CC80G476ME19L; Vendor: Murata
C102 C117 C118 C124 C126 C133 C145 C335 C336 C521 C523 C524 C526 C528 C531 = CAP_NP_0: Desc: CAP CER .10UF 10V X7R 0402; Part Num: C1005X7R1A104K; Vendor: TDK
J30 = uSDCARD_sw: Desc: CONN MINI MICRO-SD 8PIN PCB GOLD; OPTION: DBG; Part Num: 101-00660-68-6; Vendor: Amphenol
MOV2 MOV3 = MOV-small: Desc: VARISTOR 6.4V 30A 0603; Part Num: B72500D50A60; Vendor: Epcos
R9 R10 = Res_0: Desc: RES 49.9 OHM 1/10W 1% 0402 SMD; Mfr: Generic; Part Num: ERJ-2RKF49R9X; Vendor: Panasonic
R41 = Res_0: Desc: RES 4.7K OHM 1/10W 5% 0402 SMD; Mfr: Generic; Part Num: ERJ-2GEJ472X; Vendor: Panasonic
R42 = RES: $LOCATION: R169; $SEC: 1; $TOLERENCE: ?; CDS_LIB: resistors; CDS_LOCATION: R169; CDS_SEC: 1; DRAWING: @ASPENITE_LIB.ASPENITE(SCH_1):PAGE21; Desc: RES 240 OHM 1/10W 1% 0402 SMD; LOCATION: R169; MATERIAL: CH; PACK_TYPE: RES0402; PART_NUMBER: R00017-001; PATH: I450; PHYS_PAGE: 6; Part Num: ERJ-2RKF2400X; ROT: 2; SEC: 1; TOL: 5%; VER: 1; Vendor: Panasonic; WATTAGE: 1/16W; XY: (3175,2075)
R44 = Res_0: Desc: RES 100K OHM 1/16W 5% 0402 SMD; Mfr: Generic; Part Num: CRCW0402100KJNED; Vendor: Vishay
U2 = DDR3_X16_BGA96: Desc: IC DDR3 1Gbit-64Mx16; MATERIAL: IC; Part Num: MT41K64M16TW-107:J; Part Num2: NT5CB64M16FP-CF; Vendor: Micron; Vendor2: Nanya
U126 = M25P64-MLP8: Desc: IC FLASH 256MBIT 104MHZ 8WSON; Part Num: MX25L25635FZ2I-10G; Vendor: Macronix
A2 = ANT2B-JOHANSON: antenna dual-band-wifi; Desc: ANTENNA DUAL 2.45/5.4GHz; Part Num: 2450AD46A5400; Vendor: Johanson
C123 C140 = CAP_NP_0: Desc: CAP CER 1UF 10V 10% X5R 0402; Part Num: C1005X5R1A105K050BB; Vendor: TDK; ccc: CAP CER 1UF 10V 10% X5R 0402
C197 = CAP_NP: Desc: CAP CER 10000PF 16V 10% X7R 0402; Mfr: Murata; Part Num: GRM155R71C103KA01D; Vendor: Murata
C386-C389 = CAP_NP: Desc: CAP CER 0.047UF 16V 10% X7R 0402; Mfr: Murata; Part Num: C1005X7R1C473K050BC; Vendor: TDK
C536 = CAP_NP_0: Desc: CAP CER 0.3PF 200V NP0 0402; Part Num: 201R07S0R3AV4T; Tolerance: 10%; Vendor: Johanson
C537 = CAP_NP_0: Desc: CAP CER 1.5PF 200V NP0 0402; Part Num: 201R07S1R5BV4T; Tolerance: 10%; Vendor: Johanson
L2 L40 = INDUCTOR: Desc: FIXED IND 2.2NH 300MA 160 MOHM; Part Num: L-07C2N2SV6T; Vendor: Johanson
L38 L39 = INDUCTOR_0: Desc: FIXED IND 2.2UH 2A 75 MOHM SMD; Part Num: 252012CDMCDS-2R2MC; Vendor: Sumida
L41 = INDUCTOR: Desc: FIXED IND 3.9NH 300MA 220 MOHM; Part Num: L-07C3N9SV6T; Vendor: Johanson
LED13-LED15 = LED_0: Colour: *LED0603; Desc: LED GREEN CLEAR THIN 0603 SMD; OPTION: DBG; Part Num: LTST-C191KGKT; Vendor: Liteon
R126 R648 R659 = Res_0: Desc: RES 0.0 OHM 1/10W 0402 SMD; Part Num: ERJ-2GE0R00X; Vendor: Panasonic; ccc: RES 0.0 OHM 1/10W 0402 SMD
R138 R332 = R_0: Desc: RES 0.0 OHM 1/10W 0603 SMD; Mfr: Generic; Part Num: ERJ-3GEY0R00V; Vendor: Panasonic
R272 = Res_0: Desc: RES 100K OHM 1/16W 5% 0402 SMD; Part Num: CRCW0402100KJNED; Vendor: Vishay
R651 R652 = Res_0: Desc: RES SMD 150 OHM 5% 1/10W 0402; OPTION: DBG; Part Num: ERJ-2GEJ151X; Part Number: R1030402; Vendor: Panasonic
R655-R658 = R_0: Desc: RES SMD 47K OHM 5% 1/20W 0201; Mfr: Generic; Part Num: MCR006YRTJ473; Vendor: Rohm
U192 = AW-CH387
U193 = SG-3040JC: Desc: OSC 32.768KHz; Vendor: Epson
C115 = CAP_NP_2: Desc: CAP CER 10UF 10V 10% X5R 0603; Part Num: C1608X5R1A106K080AC; Vendor: TDK
C119 C125 C127 = CAP_NP_2: Desc: CAP CER 10UF 6.3V 20% X5R 0402; Part Num: C1005X5R0J106M050BC; Vendor: TDK
C128-C131 = CAP_NP_0: Desc: CAP 100pF 10% 0402 25V X7R; Part Num: ECJ-0EB1E101K; Vendor: Panasonic
C337 C384 C385 C390 = CAP_NP_0: Desc: CAP CER 33PF 50V 5% NP0 0402; Part Num: C1005C0G1H330J050BA; Vendor: TDK
CM2 CM5-CM7 = CMC_2L: Desc: CHOKE COMMON MODE 180 OHM 0805; OPTION: LIPO; Part Num: DLW21HN181SQ2L; Vendor: Murata; x: CHOKE COMMON MODE 180 OHM 0805
J27 = CON2: Desc: CONN HEADER PH SIDE 2POS 2MM SMD; Part Num: S2B-PH-SM4-TB(LF)(SN); Vendor: JST
J51 J52 = CON2: Desc: CONN HEADER ACH SIDE 2POS 1.2MM; Part Num: BM02B-ACHSS-GAN-TF(LF)(SN); Vendor: JST
Q176 = CMOS-DUAL: Desc: MOSFET N/P-CH 20V 600/350 SC89-6; Vendor: Vishay
R74 R391 = Res_0: Desc: RES 1.5K OHM 1/10W 5% 0402 SMD; Part Num: ERJ-2GEJ152X; Vendor: Panasonic; ccc: RES 0.0 OHM 1/10W 0402 SMD
U8 = AUD155_V3B: Desc: IC CODEC HP STEREO HP SPKR DRVR; Part Num: 88CE156A0NAJ2C000; Vendor: Marvell
U186 U187 = CM1293A: Desc: TVS DIODE 5.5VWM 12VC SOT26; Vendor: Diodes
J48 = CONN_FLEX_51: Desc: CONN FPC 51POS 0.30MM R/A; Part Num: 5025985193; Vendor: Molex
R145 = Res_0: Desc: RES 3.3K OHM 1/10W 5% 0402 SMD; Mfr: Generic; Part Num: ERJ-2GEJ332X; Vendor: Panasonic
RP13-RP19 = RPACK4: Desc: RES ARRAY 51 OHM 5% 4 RES SMD; Part Num: EXB-28V510JX; Vendor: Panasonic; fff: RES ARRAY 150 OHM 5% 4 RES SMD
C110 C112 C326 C391 = CAPACITOR_NON-POL: Desc: CAP CER .10UF 10V X7R 0402; OPTION: DBG; Part Num: C1005X7R1A104K; Vendor: TDK
C325 C504 C505 = CAP_NP_2: Desc: CAP CER 2.2UF 10V 10% X5R 0402; Part Num: C1005X5R1A225K; Vendor: TDK
C381 = CAP_NP_0: Desc: CAP CER 4.7UF 10V 10% X5R 0603; OPTION: LIPO; Part Num: LMK107BJ475KA-T; Vendor: Taiyo
CM4 = CMC_2L_1-2_3-4: Desc: Common Mode Choke 0.38uH 31mR 2.3A; Vendor: Coilcraft
D29 D30 = DIODE_SCHOTTKY: Desc: DIODE ESD PROT 1A 100V MICROSMP; Vendor: Vishay
J7 = CN_JTAG_MARVELL16: Desc: CONN SOCKET 2.54MM 16POS GOLD; OPTION: DBG; Part Num: HLE-108-02-F-DV; Vendor: Samtec
J33 = USB_MICRO_AB: Desc: CONN RCPT MINIUSB B 5POS SMD R/A; Part Num: 0513870530; Vendor: MOLEX
Q151-Q153 Q178 Q180 = NMOS-DUAL6-sc70: Desc: MOSFET 2N-CH 25V 0.22A SC70-6; Vendor: Fairchild
R253 = RESISTOR: Desc: RES 820 OHM 1/10W 1% 0402 SMD; OPTION: DBG; Part Num: ERJ-2RKF8200X; Vendor: Panasonic
R257 R566 = RESISTOR: OPTION: DBG; Part Num: ERJ-2GEJ220X; Vendor: Panasonic; desc: RES 22 OHM 1/10W 5% 0402 SMD
R270 = Res_0: Desc: RES 2.2K OHM 1/10W 5% 0402 SMD; OPTION: DBG; Part Num: ERJ-2GEJ222X; Part Number: R1030402; Vendor: Panasonic
R554-R556 = Res_0: Desc: RES 0.0 OHM 1/10W 0402 SMD; Part Num: ERJ-2GE0R00X; Vendor: Panasonic
R557 R623-R625 R628 R629 R632 = Res_0: Desc: RES 10K OHM 1/10W 5% 0402 SMD; Part Num: ERJ-2GEJ103X; Vendor: Panasonic
R558 = Res_0: Desc: RES 1K OHM 1/10W 5% 0402 SMD; Part Num: ERJ-2GEJ102X; Vendor: Panasonic
SC1-SC16 = EMI_CLIP: Desc: mech, clip for emi shield, ez-shield; Part Num: S0991-46R; Vendor: harwin
SW5 = SW_PUSHBUTTON-SPST-2_0: LT SWITCH SIDE PUSH SMD; Desc: SWITCH TACTILE SPST-NO 0.05A 12V; Manufacturer: Panasonic; Manufacturer_PN: EVQ-PUJ02K; Vendor: Tyco
U134 = FT234-DFN12: Part Num: FT234XD-R
D36 D37 = Diode: Desc: DIODE SCHOTTKY 30V 0.2A SOD523F; Vendor: Fairchild
D38 = DIODE_ZENER_AK: Desc: DIODE ZENER 8.51V 500MW SOD323F; Part Num: DDZ9V1ASF-7; Vendor: diodes
R567 R570 R573 R575 R577 R579 = Res_0: Desc: RES 10K OHM 1/20W 5% 0201 SMD; Part Num: ERJ-1GEJ103C; Vendor: Panasonic
R568 R571 = Res_0: Desc: RES 10K OHM 1/20W 5% 0201 SMD; Mfr: Generic; Part Num: ERJ-1GEJ103C; Vendor: Panasonic
R574 R576 R578 R580 = Res_0: Desc: RES 100K OHM 1/20W 5% 0201 SMD; Mfr: Generic; Part Num: ERJ-1GEJ104C; Vendor: Panasonic

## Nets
FLX1_3VENH/5VENL: U1.E13(MFP_26_(FN0)) ; also on sheet 17
FLX2_3VENH/5VENL: U1.A15(MFP_22_(FN5)) ; also on sheet 19
GND: C7.2 C8.2 C9.2 C12.2 C13.2 C14.2 C23.2 C24.2 C25.2 C26.2 C27.2 C29.2 C30.1 C31.2 C32.1 C33.2 C35.2 C36.2 C37.2 C38.2 C41.2 C42.2 C43.2 C44.2 C45.2 C47.2 C48.2 C51.1 C52.2 C53.2 C54.2 C55.2 C56.2 C57.2 C58.2 C59.2 C60.2 C66.1 C68.2 C69.2 C70.2 C71.2 C72.2 C73.2 C74.2 C77.2 C78.2 C80.2 C81.2 C82.2 C85.2 C86.2 C87.2 C88.2 C89.2 C90.2 C91.2 C92.2 C97.2 C101.2 C102.2 C110.2 C112.2 C114.1 C115.2 C116.1 C117.1 C118.1 C119.2 C120.1 C121.1 C122.1 C124.1 C125.2 C126.1 C127.2 C128.2 C129.2 C130.2 C131.2 C133.2 C140.2 C143.2 C144.2 C145.2 C172.2 C173.2 C177.2 C197.2 C325.2 C326.2 C339.2 C374.2 C375.2 C381.2 C383.2 C384.1 C385.1 C391.2 C500.2 C501.2 C502.2 C503.2 C505.1 C520.2 C521.2 C522.2 C523.2 C524.2 C525.2 C526.2 C527.2 C528.2 C531.2 C537.2 CM4.4(IN2) D38.A(ANODE) J7.4(GND) J7.6(GND) J7.8(GND) J7.10(GND) J7.12(GND) J7.14(GND) J7.16(GND) J30.6(VSS) J30.9(MTG9) J30.10(MTG10) J48.5 J48.6 J48.13 J48.20 J48.27 J48.34 J48.51 J48.M1 J48.M2 L40.2 MOV3.1 Q3.2(E) Q3.3(C) Q5.S Q150.1(S) Q150.4(S) Q157.1(S) Q176.1(S) Q180.1(S) R4.2 R6.2 R12.1 R15.1 R16.1 R40.2 R41.2 R42.2(B) R46.1 R54.1 R69.1 R124.2 R125.2 R145.2 R391.2 R479.1 R526.2 R528.2 R558.1 R629.2 SC1.1 SC1.2 SC1.3 SC2.1 SC2.2 SC2.3 SC3.1 SC3.2 SC3.3 SC4.1 SC4.2 SC4.3 SC5.1 SC5.2 SC5.3 SC6.1 SC6.2 SC6.3 SC7.1 SC7.2 SC7.3 SC8.1 SC8.2 SC8.3 SC9.1 SC9.2 SC9.3 SC10.1 SC10.2 SC10.3 SC11.1 SC11.2 SC11.3 SC12.1 SC12.2 SC12.3 SC13.1 SC13.2 SC13.3 SC14.1 SC14.2 SC14.3 SC15.1 SC15.2 SC15.3 SC16.1 SC16.2 SC16.3 SW5.2 SW5.4 U1.C6(VSS_1) U1.C10(VSS_2) U1.C16(VSS_52) U1.F7(VSS_53) U1.F8(VSS_54) U1.F9(VSS_55) U1.F10(VSS_56) U1.F11(VSS_57) U1.F12(VSS_58) U1.G6(VSS_59) U1.G7(VSS_3) U1.G8(VSS_4) U1.G9(VSS_5) U1.G10(VSS_6) U1.G11(VSS_7) U1.G12(VSS_8) U1.G13(VSS_60) U1.H6(VSS_61) U1.H7(VSS_9) U1.H8(VSS_10) U1.H9(VSS_11) U1.H10(VSS_12) U1.H11(VSS_13) U1.H12(VSS_14) U1.H13(VSS_62) U1.J6(VSS_63) U1.J7(VSS_15) U1.J8(VSS_16) U1.J9(VSS_17) U1.J10(VSS_18) U1.J11(VSS_19) U1.J12(VSS_20) U1.J13(VSS_64) U1.K6(VSS_65) U1.K7(VSS_21) U1.K8(VSS_22) U1.K9(VSS_23) U1.K10(VSS_24) U1.K11(VSS_25) U1.K12(VSS_26) U1.K13(VSS_66) U1.L6(VSS_67) U1.L7(VSS_27) U1.L8(VSS_28) U1.L9(VSS_29) U1.L10(VSS_30) U1.L11(VSS_31) U1.L12(VSS_32) U1.L13(VSS_68) U1.L18(VSS_33) U1.M6(VSS_69) U1.M7(VSS_34) U1.M8(VSS_35) U1.M9(VSS_36) U1.M10(VSS_37) U1.M11(VSS_38) U1.M12(VSS_39) U1.M13(VSS_70) U1.N7(VSS_40) U1.N8(VSS_41) U1.N11(VSS_42) U1.N12(VSS_43) U1.N14(VSS_74) U1.N16(VSS_80) U1.P5(VSS_75) U1.P7(VSS_44) U1.P12(VSS_45) U1.P14(VSS_76) U1.P15(VSS_82) U1.T2(VSS_46) U1.T4(VSS_47) U1.T8(VSS_48) U1.T11(VSS_49) U1.T14(VSS_50) U1.T16(VSS_77) U1.U6(VSS_51) U1.V16(VSS_81) U2.A9(VSS_1) U2.B1(VSSQ_1) U2.B3(VSS_2) U2.B9(VSSQ_2) U2.D1(VSSQ_3) U2.D8(VSSQ_4) U2.E1(VSS_3) U2.E2(VSSQ_5) U2.E8(VSSQ_6) U2.F9(VSSQ_7) U2.G1(VSSQ_8) U2.G8(VSS_4) U2.G9(VSSQ_9) U2.J2(VSS_5) U2.J8(VSS_6) U2.M1(VSS_7) U2.M9(VSS_8) U2.P1(VSS_9) U2.P9(VSS_10) U2.T1(VSS_11) U2.T9(VSS_12) U8.17(DGND) U8.33(GND_PAD) U126.4(VSS) U126.9(TPAD) U134.5(GND) U134.13(GNDPAD) U186.2(NV) U187.2(NV) U192.A2(GND) U192.B1(GND) U192.B2(GND) U192.B3(GND) U192.B5(GND) U192.C2(GND) U192.C3(GND) U192.C4(GND) U192.G7(GND) U192.G8(GND) U192.H6(GND) U192.H7(GND) U192.H8(GND) U192.J4(GND) U192.J5(GND) U192.J6(GND) U192.J7(GND) U192.J8(GND) U192.J9(GND) U192.J10(GND) U192.K4(GND) U192.K9(GND) U193.2(GND) ; also on sheet 10 13 14 16 17 18 19
GND_SER: CM4.3(OUT2) D29.1(ANODE) D30.1(ANODE) J33.5(GND) J33.T3(TAB) J33.T4(TAB) J33.T5(TAB) J33.T6(TAB) MOV2.1
V1P1I_WIFI: C144.1 C145.1 L39.1 U192.A3(VBUCK11_IN)
V1P1O_WIFI: L39.2 U192.A4(VBUCK11_OUT)
V1P2_MAU: C118.2 C119.1 U8.16(DCVDD)
V1P5_DDR: C85.1 C86.1 C87.1 C88.1 C89.1 C90.1 C91.1 C92.1 C101.1 C172.1 Q148.1(S1) R44.2 R45.2 U2.A1(VDDQ_1) U2.A8(VDDQ_2) U2.B2(VDD_1) U2.C1(VDDQ_3) U2.C9(VDDQ_4) U2.D2(VDDQ_5) U2.D9(VDD_2) U2.E9(VDDQ_6) U2.F1(VDDQ_7) U2.G7(VDD_3) U2.H2(VDDQ_8) U2.H9(VDDQ_9) U2.K2(VDD_4) U2.K8(VDD_5) U2.N1(VDD_6) U2.N9(VDD_7) U2.R1(VDD_8) U2.R9(VDD_9) ; also on sheet 10
V1P5_DDR_A: C8.1 C35.1 C36.1 C37.1 C38.1 C41.1 C42.1 C43.1 C44.1 C45.1 C47.1 C48.1 C51.2 C173.1 Q148.6(D1) Q148.7(D1a) Q155.5(G) R7.1 R11.1 R13.2 R14.1 R281.2 TP23.1(TP) U1.P9(VDD_M_1) U1.R2(VDD_M_2) U1.R4(VDD_M_3) U1.T7(VDD_M_4) U1.T10(VDD_M_5) U1.T13(VDD_M_6) U1.U3(VDD_M_7) U1.U5(VDD_M_8)
V1P8: C177.1 FB51.1 Q156.1(S1) Q159.1(S1) R68.1 ; also on sheet 10
V1P8_MAU: C124.2 C125.1 FB6.2 U8.24(HPVDD)
V1P8_OSC: C23.1 C24.1 C80.1 FB15.2 FB51.2 TP25.1(TP) U1.P16(AVDD_OSC)
V1P8I_WIFI: C527.1 C528.1 L38.1 U192.C1(VBUCK18_IN)
V1P8O_WIFI: L38.2 U192.D1(VBUCK18_OUT)
V3P3: C12.1 C13.1 C14.1 C25.1 C26.1 C27.1 C29.1 C30.2 C77.1 C102.1 C374.1 C375.1 C386.2 C387.2 C388.2 C389.2 J7.1(V_REF) J7.2(V_SUP) J30.4(VDD) MOV3.2 Q148.4(S2) Q151.2(G) Q151.5(G) Q152.2(G) Q152.5(G) Q153.2(G) Q153.5(G) Q159.4(S2) Q178.5(G) R1.1 R38.1 R50.1 R52.1 R73.2 R82.2 R83.2 R84.2 R101.2 R138.1 R270.2 R316.2 R317.2 R477.2 R556.1 R567.2 R570.2 R573.2 R575.2 R577.2 R579.2 R623.2 R628.2 R632.1 R633.2 R639.1 U1.C4(VDD_IO2_1) U1.C7(VDD_IO2_2) U1.C9(VDD_IO2_3) U1.E5(VDD_IO4_1) U1.E14(VDD_IO0_2) U1.F5(VDD_IO4_2) U1.F14(VDD_IO0_1) U1.J5(VDD_IO3_1) U1.J14(VDD_IO1_2) U1.K5(VDD_IO3_2) U1.K14(VDD_IO1_1) U126.8(VCC) ; also on sheet 10 13 14 16 17 18 19
V3P3_MAU: C126.2 C127.1 FB5.1 Q176.2(G) R332.2 R528.1 U8.18(DBVDD)
V3P3_MAUAVDD: C114.2 FB5.2 U8.3(AVDD_BYP)
V3P3_NFC: C531.1 FB56.1 U192.E1(3V3_NFC_IN)
V3P3_USB_A: C31.1 C32.2 C33.1 C78.1 Q148.3(D2) Q148.8(D2a) TP24.1(TP) U1.M16(AVDD_USB_UHC) U1.N15(AVDD_USB_OTG) ; also on sheet 14
V3P3_WIFI: C133.1 C143.1 FB45.2 FB53.2 FB54.2 FB55.2 FB56.2 R138.2 R272.2 R651.2 R652.2 R655.1 R656.1 R657.1 R658.1 U192.A1(VBAT)
V3P3_WIFI_RF: C521.1 C522.1 FB45.1 U192.H10(3V3_RF_IN)
V3P3_WIFI_VIO: C197.1 C523.1 FB55.1 R126.2 R648.2 R649.1 R650.1 U192.C10(VIO)
V3P3_WIFI_VIORF: C524.1 FB54.1 U192.J1(VIO_RF)
V3P3_WIFI_VIOSD: C525.1 C526.1 FB53.1 U192.B4(VIO_SD)
V3P3FTDI: C112.1 Q178.2(G) Q180.2(G) Q180.5(G) R555.2 R556.2 R557.2 R624.2 R625.2 R629.1 U134.9(VCCIO)
V3P3U: C110.1 R555.1 U134.3(3V3OUT)
V5P0_MAU_PA: C115.1 C117.2 FB4.2 U8.26(SPKVDD2) U8.29(SPKVDD1)
VBUS_SER: C325.1 C326.1 C381.1 CM4.1(IN1) R253.1 U134.4(VCC) ; also on sheet 13
VBUS_SER_CONN: CM4.2(OUT1) J33.1(VBUS) MOV2.2
VCC_FLEX1: R574.1 R576.1 ; also on sheet 17
VCC_FLEX2: R578.1 R580.1 ; also on sheet 19
VIN: D36.1(C1) ; also on sheet 13 16
2G5G_WLAN_BT: C536.1 L41.2 U192.K10(ANT_2G5GBT)
AICSPCLK1: Q151.4(S) R575.1 U1.B15(MFP_21_(FN5))
AICSPCLK2: Q152.4(S) R579.1 U1.D18(MFP_8)
AICSPDAT1: Q151.1(S) R573.1 U1.A17(MFP_17_(FN5))
AICSPDAT2: Q152.1(S) R577.1 U1.C17(MFP_13_(FN5))
AP_PRI_TCK: J7.9(TCK) ; also on sheet 14
AP_PRI_TDI: J7.5(TDI) ; also on sheet 14
AP_PRI_TDO: LED13.2(K) R257.1 ; also on sheet 14
AP_PRI_TMS: J7.7(TMS) ; also on sheet 14
AP_TRST_N: J7.3(TRST#) ; also on sheet 14
AP_UART2_CBUS0: Q180.3(D) R628.1 U1.C14(MFP_24_(FN5))
AP_UART2_RX: J48.44 Q178.4(S) R623.1 ; also on sheet 14
AP_UART2_TX: J48.45 Q178.6(D) ; also on sheet 14
AP_UART2_VBUS_L: Q180.6(D) R632.2 U1.B16(MFP_18_(GPO_UD)(FN0))
ASPEN_DDR_RST#: Q155.4(S) R7.2 R336.2 U1.V14(VSS_(M_RST#_OUTPUT))
AUDIO_ADCDAT: U8.13(SDOUT) ; also on sheet 14
AUDIO_BCLK: U8.12(BCLK) ; also on sheet 14
AUDIO_DACDAT: U8.14(SDIN) ; also on sheet 14
AUDIO_LRCK: U8.15(LRCK) ; also on sheet 14
AUDIO_MCLK: U8.11(MCLK) ; also on sheet 14
BT2AP_WAKEUP: U192.C7(GPIO13)
BT_LED: LED14.2(K) U192.H3(LED_OUT_BT)
CE156ON_L: Q159.2(G1) Q159.5(G2) R526.1 R639.2 ; also on sheet 14
CON_MIC1N: CM5.1(IN1) J27.2 U187.4(CH3)
CON_MIC1P: CM5.2(OUT1) J27.1 U187.3(CH2)
CON_OUT_L: C128.1 CM6.4(IN2) J51.2 U186.3(CH2)
CON_OUT_LN: C129.1 CM6.3(OUT2) J51.1 U186.1(CH1)
CON_OUT_R: C130.1 CM7.4(IN2) J52.2 U186.6(CH4)
CON_OUT_RN: C131.1 CM7.3(OUT2) J52.1 U186.4(CH3)
CON_USBDM: CM2.3(OUT2) D29.2(CATHODE) J33.2(D-)
CON_USBDP: CM2.4(IN2) D30.2(CATHODE) J33.3(D+)
DDR_BA0: U1.T9(M_BA0) U2.M2(BA0)
DDR_BA1: U1.R9(M_BA1) U2.N8(BA1)
DDR_BA2: U1.P10(M_BA2) U2.M3(BA2)
DDR_CALPAD: R6.1 U1.N4(CALPAD)
DDR_CAS#: U1.V9(M_CAS#) U2.K3(CAS_N)
DDR_CKE0: R41.1 U1.R7(M_CKE0) U2.K9(CKE)
DDR_CLK: R10.2 U1.V6(M_CLK0) U2.J7(CK_P)
DDR_CLK#: R9.2 U1.V7(M_CLK0#) U2.K7(CK_N)
DDR_CS0#: U1.R8(M_CS0#) U2.L2(CS_N)
DDR_DQ0: U1.P2(MDQ0) U2.E3(DQ0)
DDR_DQ1: U1.P3(MDQ1) U2.F7(DQ1)
DDR_DQ2: U1.P4(MDQ2) U2.F2(DQ2)
DDR_DQ3: U1.R3(MDQ3) U2.F8(DQ3)
DDR_DQ4: U1.T3(MDQ4) U2.H3(DQ4)
DDR_DQ5: U1.U1(MDQ5) U2.H8(DQ5)
DDR_DQ6: U1.U2(MDQ6) U2.G2(DQ6)
DDR_DQ7: U1.V1(MDQ7) U2.H7(DQ7)
DDR_DQ8: U1.V3(MDQ8) U2.D7(DQ8)
DDR_DQ9: U1.U4(MDQ9) U2.C3(DQ9)
DDR_DQ10: U1.R5(MDQ10) U2.C8(DQ10)
DDR_DQ11: U1.T5(MDQ11) U2.C2(DQ11)
DDR_DQ12: U1.P6(MDQ12) U2.A7(DQ12)
DDR_DQ13: U1.R6(MDQ13) U2.A2(DQ13)
DDR_DQ14: U1.T6(MDQ14) U2.B8(DQ14)
DDR_DQ15: U1.U7(MDQ15) U2.A3(DQ15)
DDR_DQM0: U1.P1(M_DQM0) U2.E7(LDM)
DDR_DQM1: U1.V2(M_DQM1) U2.D3(UDM)
DDR_DQS0: R12.2 U1.T1(M_DQS0) U2.F3(LDQS_P)
DDR_DQS0#: R11.2 U1.R1(M_DQS0#) U2.G3(LDQS_N)
DDR_DQS1: R15.2 U1.V5(M_DQS1) U2.C7(UDQS_P)
DDR_DQS1#: R14.2 U1.V4(M_DQS1#) U2.B7(UDQS_N)
DDR_MA0: U1.R10(MA0) U2.N3(CA0)
DDR_MA1: U1.U10(MA1) U2.P7(CA1)
DDR_MA2: U1.V10(MA2) U2.P3(CA2)
DDR_MA3: U1.R11(MA3) U2.N2(CA3)
DDR_MA4: U1.U11(MA4) U2.P8(CA4)
DDR_MA5: U1.V11(MA5) U2.P2(CA5)
DDR_MA6: U1.V12(MA6) U2.R8(CA6)
DDR_MA7: U1.U12(MA7) U2.R2(CA7)
DDR_MA8: U1.T12(MA8) U2.T8(CA8)
DDR_MA9: U1.R12(MA9) U2.R3(CA9)
DDR_MA10: U1.V13(MA10) U2.L7(CA10)
DDR_MA11: U1.U13(MA11) U2.R7(CA11)
DDR_MA12: U1.R13(MA12) U2.N7(CA12)
DDR_MA13: U1.P13(MA13) U2.T3(CA13)
DDR_MA14: U1.R14(MA14) U2.T7(CA14)
DDR_ODT0: U1.U8(M_ODT0) U2.K1(ODT)
DDR_RAS#: U1.V8(M_RAS#) U2.J3(RAS_N)
DDR_RST#: Q155.3(D) R44.1 R336.1 U2.T2(RESET_N)
DDR_VREF_ASPEN: C9.1 R13.1 R16.2 U1.N1(VREF)
DDR_WE#: U1.U9(M_WE#) U2.L3(WE_N)
EXP_OC_L: U1.D16(MFP_10_(FN5)) ; also on sheet 18
FLX1_OC_L: U1.D15(MFP_11_(FN5)) ; also on sheet 17
FLX2_OC_L: U1.C18(MFP_12_(FN5)) ; also on sheet 19
FM_ANT_RX_GND: U192.E10(FM_ANT_RX_GND)
FT_RST_L: C391.1 R253.2 R558.2 U134.2(RESETL)
HSI_0: R124.1 R649.2 U192.K6(GPIO2/CON0)
HSI_1: R125.1 R650.2 U192.K5(I2S_CCLK/PCM_MCLK/GPIO3/CON1)
ICSPCLK1: Q151.3(D) R576.2 ; also on sheet 17
ICSPCLK2: Q152.3(D) R580.2 ; also on sheet 19
ICSPDAT1: Q151.6(D) R574.2 ; also on sheet 17
ICSPDAT2: Q152.6(D) R578.2 ; also on sheet 19
LCD_DD0: RP16.7(R7) U1.E10(MFP_60_(LCD_DD0)_(FN1))
LCD_DD1: RP17.1(R1) U1.D10(MFP_61_(LCD_DD1)_(FN1))
LCD_DD2: RP18.7(R7) U1.B10(MFP_62_(LCD_DD2)_(FN1))
LCD_DD3: RP13.1(R1) U1.A10(MFP_63_(LCD_DD3)_(FN1))
LCD_DD4: RP13.3(R3) U1.A9(MFP_64_(LCD_DD4)_(FN1))
LCD_DD5: RP18.5(R5) U1.B9(MFP_65_(LCD_DD5)_(FN1))
LCD_DD6: RP16.5(R5) U1.D9(MFP_66_(LCD_DD6)_(FN1))
LCD_DD7: RP17.3(R3) U1.E9(MFP_67_(LCD_DD7)_(FN1))
LCD_DD8: RP16.3(R3) U1.A8(MFP_68_(LCD_DD8)_(FN1))
LCD_DD9: RP17.7(R7) U1.B8(MFP_69_(LCD_DD9)_(FN1))
LCD_DD10: RP17.5(R5) U1.C8(MFP_70_(LCD_DD10)_(FN1))
LCD_DD11: RP16.1(R1) U1.D8(MFP_71_(LCD_DD11)_(FN1))
LCD_DD12: RP15.1(R1) U1.A7(MFP_72_(LCD_DD12)_(FN1))
LCD_DD13: RP15.3(R3) U1.B7(MFP_73_(LCD_DD13)_(FN1))
LCD_DD14: RP15.5(R5) U1.D7(MFP_74_(LCD_DD14)_(FN1))
LCD_DD15: RP14.3(R3) U1.E7(MFP_75_(LCD_DD15)_(FN1))
LCD_DD16: RP14.7(R7) U1.A6(MFP_76_(LCD_DD16)_(FN1))
LCD_DD17: RP14.5(R5) U1.B6(MFP_77_(LCD_DD17)_(FN1))
LCD_DD18: RP14.1(R1) U1.D6(MFP78_(LCD_DD18)_(FN1))
LCD_DD19: RP19.7(R7) U1.E6(MFP79_(LCD_DD19)_(FN1))
LCD_DD20: RP19.3(R3) U1.A5(MFP80_(LCD_DD20)_(FN1))
LCD_DD21: RP19.1(R1) U1.B5(MFP81_(LCD_DD21)_(FN1))
LCD_DD22: RP19.5(R5) U1.C5(MFP82_(LCD_DD22)_(FN1))
LCD_DD23: RP13.5(R5) RP15.7(R7) U1.D5(MFP83_(LCD_DD23)_(FN1))
LCD_DENA_SMPNVS: R520.2 U1.A11(MFP_59_(LCD_DENA_BIAS)_(FN1))
LCD_LCLK_A0: RP18.1(R1) U1.C11(MFP_57_(LCD_LCLK_A0)_(FN1))
LCD_PCLK_WRB: RP13.7(R7) U1.B11(MFP_58_(LCD_PCLK_WR)_(FN1))
LCD_PWM: J48.4 R145.1 U1.A4(MFP84_(PWM1_BL_CONTROL)_(FN4))
LCD_RST2: R333.2 U1.B4(MFP85_(GPO_BL_PWREN)_(FN0))
LCD_VFCLK_RDB: RP18.3(R3) U1.D11(MFP_56_(LCD_FCLK_RD)_(FN1))
LCDB_DD0: J48.7 RP16.8(R72)
LCDB_DD1: J48.8 RP17.2(R12)
LCDB_DD2: J48.9 RP18.8(R72)
LCDB_DD3: J48.10 RP13.2(R12)
LCDB_DD4: J48.11 RP13.4(R32)
LCDB_DD5: J48.12 RP18.6(R52)
LCDB_DD6: J48.14 RP16.6(R52)
LCDB_DD7: J48.15 RP17.4(R32)
LCDB_DD8: J48.16 RP16.4(R32)
LCDB_DD9: J48.17 RP17.8(R72)
LCDB_DD10: J48.18 RP17.6(R52)
LCDB_DD11: J48.19 RP16.2(R12)
LCDB_DD12: J48.21 RP15.2(R12)
LCDB_DD13: J48.22 RP15.4(R32)
LCDB_DD14: J48.23 RP15.6(R52)
LCDB_DD15: J48.24 RP14.4(R32)
LCDB_DD16_SMPNCS1: J48.25 RP14.8(R72)
LCDB_DD17_SMPNCS0: J48.26 RP14.6(R52)
LCDB_DD18_SPICS1_SMPNCS0: J48.31 RP14.2(R12)
LCDB_DD19_SPICS0: J48.39 RP19.8(R72) TP10.1(TP)
LCDB_DD20_SPIDIN: J48.37 RP19.4(R32) TP8.1(TP)
LCDB_DD21_SPIDOUT: J48.36 RP19.2(R12) TP7.1(TP)
LCDB_DD22_SPIDCLK: J48.38 RP19.6(R52) TP9.1(TP)
LCDB_DD23_BIAS_RST: J48.33 RP15.8(R72)
LCDB_DD23_DENA_BIAS: RP13.6(R52) TP6.1(TP)
LCDB_DENA_SMPNVS: J48.32 R520.1
LCDB_GPIO_RST: J48.35 R333.1 TP11.1(TP)
LCDB_LCLK_A0: J48.30 RP18.2(R12)
LCDB_PCLK_WRB: J48.29 RP13.8(R72)
LCDB_VFCLK_RDB: J48.28 RP18.4(R32)
MFP90: J48.47 ; also on sheet 14 18
MFP91: J48.48 ; also on sheet 14 18
MFP92: J48.49 ; also on sheet 14 18
MFP93: J48.50 ; also on sheet 14 18
MFP_I2C_INTR: U1.B17(MFP_15_(FN5)) ; also on sheet 18
MFP_SCL: J48.43 U8.19(SCLK) ; also on sheet 14 16 18
MFP_SDA: J48.42 U8.20(SDAT) ; also on sheet 14 16 18
MIC1N: C336.1 C390.2 U8.5(MIC1N/LINEIN_L)
MIC1N_C: C336.2 C337.2 C385.2 CM5.4(IN2) R391.1
MIC1P: C335.1 C390.1 U8.6(MIC1P)
MIC1P_C: C335.2 C337.1 C384.2 CM5.3(OUT2) R74.1
MICBIAS_M: C383.1 R74.2 U8.4(MICBIAS)
MMC3_CLK: J30.5(CLK) U1.E12(MFP36_(MMC3_CLK)_(FN6))
MMC3_CMD: J30.3(CMD) R83.1 U1.A12(MFP35_(MMC3_CMD)_(FN6))
MMC3_D0: J30.7(DAT0) R73.1 U1.E15(MFP_7_(MMC3_DAT0)_(FN6))
MMC3_D1: J30.8(DAT1) R82.1 U1.E16(MFP_6_(MMC3_DAT1)_(FN6))
MMC3_D2: J30.1(DAT2) R101.1 U1.E17(MFP_5_(MMC3_DAT2)_(FN6))
MMC3_D3: J30.2(CD/DAT3) R84.1 U1.E18(MFP_4_(MMC3_DAT3)_(FN6))
NFC_SWP1_VDDIN: U192.E3(NFC_SWP1_VDDIN)
NFC_SWP1_VOUT: U192.E2(NFC_SWP1_VOUT)
NFC_SWP2_VDDOUT: U192.D3(NFC_SWP2_VDDOUT)
OTG_CHGR33_L: U1.C13(MFP_27_(FN5)) ; also on sheet 13
RST_AP#: C339.1 J7.15(SRST#) SW5.1 SW5.3 ; also on sheet 14
SDCARD_DET: J30.11(CD11) R633.1 ; also on sheet 14
SLEEP_CLK: U192.A10(SLP_CLK_IN) U193.3(OUT)
SPI_CLK: U126.6(C) ; also on sheet 14
SPI_FRM: R465.1 ; also on sheet 14
SPI_NOR_ON: R464.1 ; also on sheet 14
SPI_RXD: U126.2(Q) ; also on sheet 14
SPI_TXD: U126.5(D) ; also on sheet 14
SPI_WP#: R52.2 R479.2 U126.3(~{W})
SPK_OUT_L: CM6.1(IN1) U8.30(SPK_LP)
SPK_OUT_LN: CM6.2(OUT1) U8.28(SPK_LN)
SPK_OUT_R: CM7.1(IN1) U8.25(SPK_RP)
SPK_OUT_RN: CM7.2(OUT1) U8.27(SPK_RN)
STAT1: U1.F18(MFP_0_(MMC3_DAT7)_(FN6)) ; also on sheet 16
STAT2: U1.F17(MFP_1_(MMC3_DAT6)_(FN6)) ; also on sheet 16
SW3: C504.1 ; also on sheet 10
TOUCH_INTR: J48.41 U1.B18(MPF_14_(FN5))
TOUCH_RST: J48.46 U1.D17(MFP_9)
UART2_CBUS0: R554.1 R557.1 U134.6(CBUS0) ; also on sheet 16
UART_USBDM: CM2.2(OUT1) U134.1(USBDM)
UART_USBDP: CM2.1(IN1) U134.12(USBDP)
VCORE: C52.1 C53.1 C54.1 C55.1 C56.1 C57.1 C58.1 C59.1 C60.1 C66.2 C68.1 C69.1 C70.1 C71.1 C72.1 C73.1 C74.1 C97.1 C388.1 C389.1 Q5.G R40.1 U1.E8(VDD_CORE_11) U1.E11(VDD_CORE_12) U1.G5(VDD_CORE_3) U1.G14(VDD_CORE_4) U1.H5(VDD_CORE_2) U1.H14(VDD_CORE_1) U1.L5(VDD_CORE_5) U1.L14(VDD_CORE_6) U1.M5(VDD_CORE_7) U1.M14(VDD_CORE_8) U1.P8(VDD_CORE_9) U1.P11(VDD_CORE_10) U1.T17(RFU_(VDD_CORE)) ; also on sheet 10
VCOREON: Q5.D Q148.2(G1) Q148.5(G2) Q156.2(G1) Q157.2(G) R38.2
VLCD: J48.1 R317.1
VLCD_BL: J48.2 J48.3 R316.1 R440.1
VPP: C500.1 C502.1 D38.K(CATHODE) Q147.1(S1) Q147.4(S2) R566.2 R568.1 R571.1 TP29.1(TP)
VPP1_CTRL: Q153.1(S) R567.1 U1.F15(MFP_3_(MMC3_DAT4)_(FN6))
VPP1_CTRLS: Q147.2(G1) Q150.2(G) Q153.6(D) R568.2
VPP2_CTRL: Q153.4(S) R570.1 U1.F16(MFP_2_(MMC3_DAT5)_(FN6))
VPP2_CTRLS: Q147.5(G2) Q150.5(G) Q153.3(D) R571.2
VPP_PIC1a: C501.1 Q147.6(D1) Q147.7(D1a) R569.2 ; also on sheet 17
VPP_PIC2a: C503.1 Q147.3(D2) Q147.8(D2a) R572.2 ; also on sheet 19
VREF_DDR: C81.1 C82.1 R45.1 R46.2 U2.H1(VREF_DQ) U2.M8(VREF_CA)
VSYS: C386.1 C387.1 R440.2 U1.P18(AVDD5_USB) ; also on sheet 10 13 17 18 19
VSYS_HIB: Q176.4(S) R527.1 U186.5(VP) U187.5(VP) ; also on sheet 10 13
VTOUCH: J48.40 R477.1
WLAN2AP_WAKEUP: U192.E8(XOSC_EN/GPIO0)
WLAN_LED: LED15.2(K) U192.J3(LED_OUT_WLAN)
WLAN_PDn: R272.1 U192.D2(PDN) ; also on sheet 14
WLAN_SD0: R655.2 U192.B8(SD_D0) ; also on sheet 14
WLAN_SD1: R656.2 U192.B9(SD_D1) ; also on sheet 14
WLAN_SD2: R657.2 U192.A8(SD_D2) ; also on sheet 14
WLAN_SD3: R658.2 U192.A9(SD_D3) ; also on sheet 14
WLAN_SDCLK: U192.A7(SD_CLK/SPI_CLK) ; also on sheet 14
WLAN_SDCMD: U192.A6(SD_CMD/SPI_DI) ; also on sheet 14
N40044826: R1.2 R4.1 U1.N5(VSS_(SEC_CS_EN))
N40391928: R68.2 R69.2 U1.T15(RFU_(AVDDT_PCIE)) U1.U16(RFU_(AVDD_PCIE))
N40401834: Q3.1(B) U1.R16(RFU_(RT_SEN))
N41867996: C140.1 R126.1 U193.4(VDD)
N41905335: FB15.1 Q156.6(D1) Q156.7(D1a)
N42190736: R42.1(A) U2.L8(ZQ)
N42554913: C123.2 U8.23(FLYP)
N42554915: C123.1 U8.21(FLYN)
N42555160: C116.2 U8.22(VSS_HP_BYP)
N42555188: C121.2 U8.2(VREF)
N42555198: C120.2 U8.7(VCM_BYP)
N42555204: C122.2 U8.8(VOCCP)
N42564866: R54.2 R464.2 R465.2 U126.1(~{S})
N42564868: R50.2 U126.7(~{HOLD})
N42756900: Q178.3(D) U134.7(TXD)
N42795329: J7.13(TDO) R257.2
N42854894: LED13.1(A) R270.1
N43488330: FB4.1 Q176.3(D)
N43488337: Q159.3(D2) Q159.8(D2a) R332.1
N43488344: FB6.1 Q159.6(D1) Q159.7(D1a)
N43489932: Q176.5(G) Q176.6(D) R527.2
N43661156: C504.2 D36.2(A) D37.1(C1)
N43661159: C505.2 D37.2(A) R566.1
N43683631: Q150.6(D) R569.1
N43683720: Q150.3(D) R572.1
N43691046: Q157.6(D) R281.1
N43967795: C7.1 R9.1 R10.1
N44150122: Q178.1(S) R624.1 U134.10(RXD)
N44156859: Q180.4(S) R554.2 R625.1
N44395511: C520.1 U192.H1(NFC_VDDANT)
N44397564: R648.1 U193.1(VIO)
N44425364: LED14.1(A) R651.1
N44425501: LED15.1(A) R652.1
N44458528: A2.2(2G_IN) L2.1
N44458546: A2.1(5G_IN) R659.2
N44458574: C537.1 L2.2 L41.1
N44458922: C536.2 L40.1 R659.1

Not connected (* = marked no-connect by the designer): A2 3(5G)* 4(2G)*; J7 11(RTCK)*; J30 12(CD12)*; J33 4(ID)*; U1 A18(MFP_16_(GPO_LR)(FN0))* C12(MFP34_(GPO_PWREN)_(FN0))* N9(VSS_(M_CKE1))* N10(VSS_(M_CS1#))* R15(RFU) U14(VSS_(M_ODT1))* U15(RFU_(PCIETX)) U17(RFU_(PCIERX)) U18(RFU_(PCIECLK)) V15(RFU_(PCIETX#)) V17(RFU_(PCIERX#)) V18(RFU_(PCIECLK#)); U2 J1(NC_1)* J9(NC_2)* L1(NC_3)* L9(NC_4)* M7(NC_5)*; U8 1(HPS)* 9(MIC2P)* 10(MIC2N/LINEIN_R)* 31(HP_R)* 32(HP_L)*; U134 8(RTS)* 11(CTS)*; U187 1(CH1)* 6(CH4)*; U192 A5(NC)* B6(NC)* B7(NC)* B10(NC)* C5(NC)* C6(NC)* C8(NC)* C9(NC)* D4(NFC_SWP1_IO)* D5(NC)* D6(NC)* D7(I2S_LRCLK/PCM_SYNC/GPIO7)* D8(I2S_BCLK/PCM_CLK/GPIO6)* D9(FM_A_OUT_L)* D10(FM_ANT_RX)* E4(NFC_SWP2_IO)* E5(GPIO12)* E6(NC)* E7(I2S_DIN/PCM_DIN/GPIO4)* E9(FM_A_OUT_R)* F1(NFC_ANT_P)* F2(NFC_TWSI_SCK)* F3(NFC_TWSi_SDA)* F4(NFC_WI_IN)* F5(UART_SO/GPIO8)* F6(NC)* F7(I2S_DO/PCM_DO/GPIO5)* F8(GPIO1)* F9(NC)* F10(NC)* G1(NFC_ANT_N)* G2(TDI/GPIO16)* G3(TDO/GPIO17)* G4(UART_CTSn/GPIO10)* G5(UART_SIN/GPIO9)* G6(NC)* G9(NC)* G10(NC)* H2(TCK/GPIO14)* H4(NC)* H5(UART_RTSn/GPIO11)* H9(NC)* J2(TMS/GPIO15)* K1(RF_CNTL2_N)* K2(RF_CNTL1_P)* K3(RF_CNTL0_N)* K7(NC)* K8(NC)*

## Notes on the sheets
sheet 1
- ASPEN - MEMORY/LCD
- DDR3 MEM
- short as possible
- Notes:
  Connect 240ohm 1% resistor to ground for
  CALPAD pin.
- DDR_VREF; Close to pin
- RES close to ASPEN as possible
sheet 2
- ASPEN - Power
- No sequencing needed
- For A0 part use R69
  For B0 part use R68
- FB15 Enable 1.8V_OSC after VCORE on
- ?Ground trace join plane near ASPEN
- Enable V1P5_DDR_A after VCORE on
  and discharge v1p5_ddr_a rail quickly
- FB51 Enable 1.8V_OSC before VCORE
- Temperature Sensor
- Enable 3.3V_USB after VCORE on
sheet 3
- Place across power plane split near WiFi signals
- BT/FM Audio
- AW-CH387 8887 WIFI
- NFC
- Place across power plane split near WiFi signals
- ECO K4R5,4: antenna tuning
- Note: tuned parts DO NOT substitute
- BT/FM Audio
- BT Ctrl
- ECO K4R5,1: osc power has no feed
sheet 4
- ECO K4R5,3: codec power dip
- ECO K4R5,3: codec power dip
- use seltech MEO6027C85-382C1033
- HP_SENSE
- NO head phone jack
- use only ONE
  seltech GO2014C4Y8GN-1
  bestar  BMS2014P-11C-08H03 LF
- I2C linux address: 0x30
- 2.For SPKVDD_EN is high(3.3V) , SPKVDD will be enable
sheet 5
- Footprint 4Gb 512Mbytes MAX
  Part Used 1Gb 128MBytes
- SANWIN uSD slot, both 11 & 12 are CD MAKE=card present
  Amphenol pin 12 is GND 11 BREAK=card present
- Card  in   out
  SW    LL    HH
  AM    HL    LL
- SD/MMC connector
- SPI NOR FLASH
- Place close to SD card connector
- Size: 128Mbit
- Close to pins
- Termination Resistor
sheet 6
- All aspen LCD + Touch signals to bridge
- PIN SWAP OK
- D0 ............................ D17
- Use Molex FPC Jumper 2in 15015-0251
- SSP3_CLK
- SSP3_FRM
- SSP3_RXD
- SSP3_TXD
- Touch controller
  I2C linux address: 0x33
sheet 7
- silkscreen TP29: VPP
- Power for micro controller
sheet 8
- Debug and console connections
- Silkscreen: console uart
- Clips for EMI shield
- Place these 8 footprints on TOP side along current shield trace
- ECO 2: Disconnected GND
- ECO 3: Footprint odd-even swap
- JTAG (inside only)
- Place these 8 footprints on BOTTOM side along current shield trace
- ECO : reduced cap size for faster rst_ap# Trise
